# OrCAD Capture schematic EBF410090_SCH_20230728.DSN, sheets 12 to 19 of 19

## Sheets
12 16 MIPI CSI PORT: size A4; note: MIPI CSI PORT
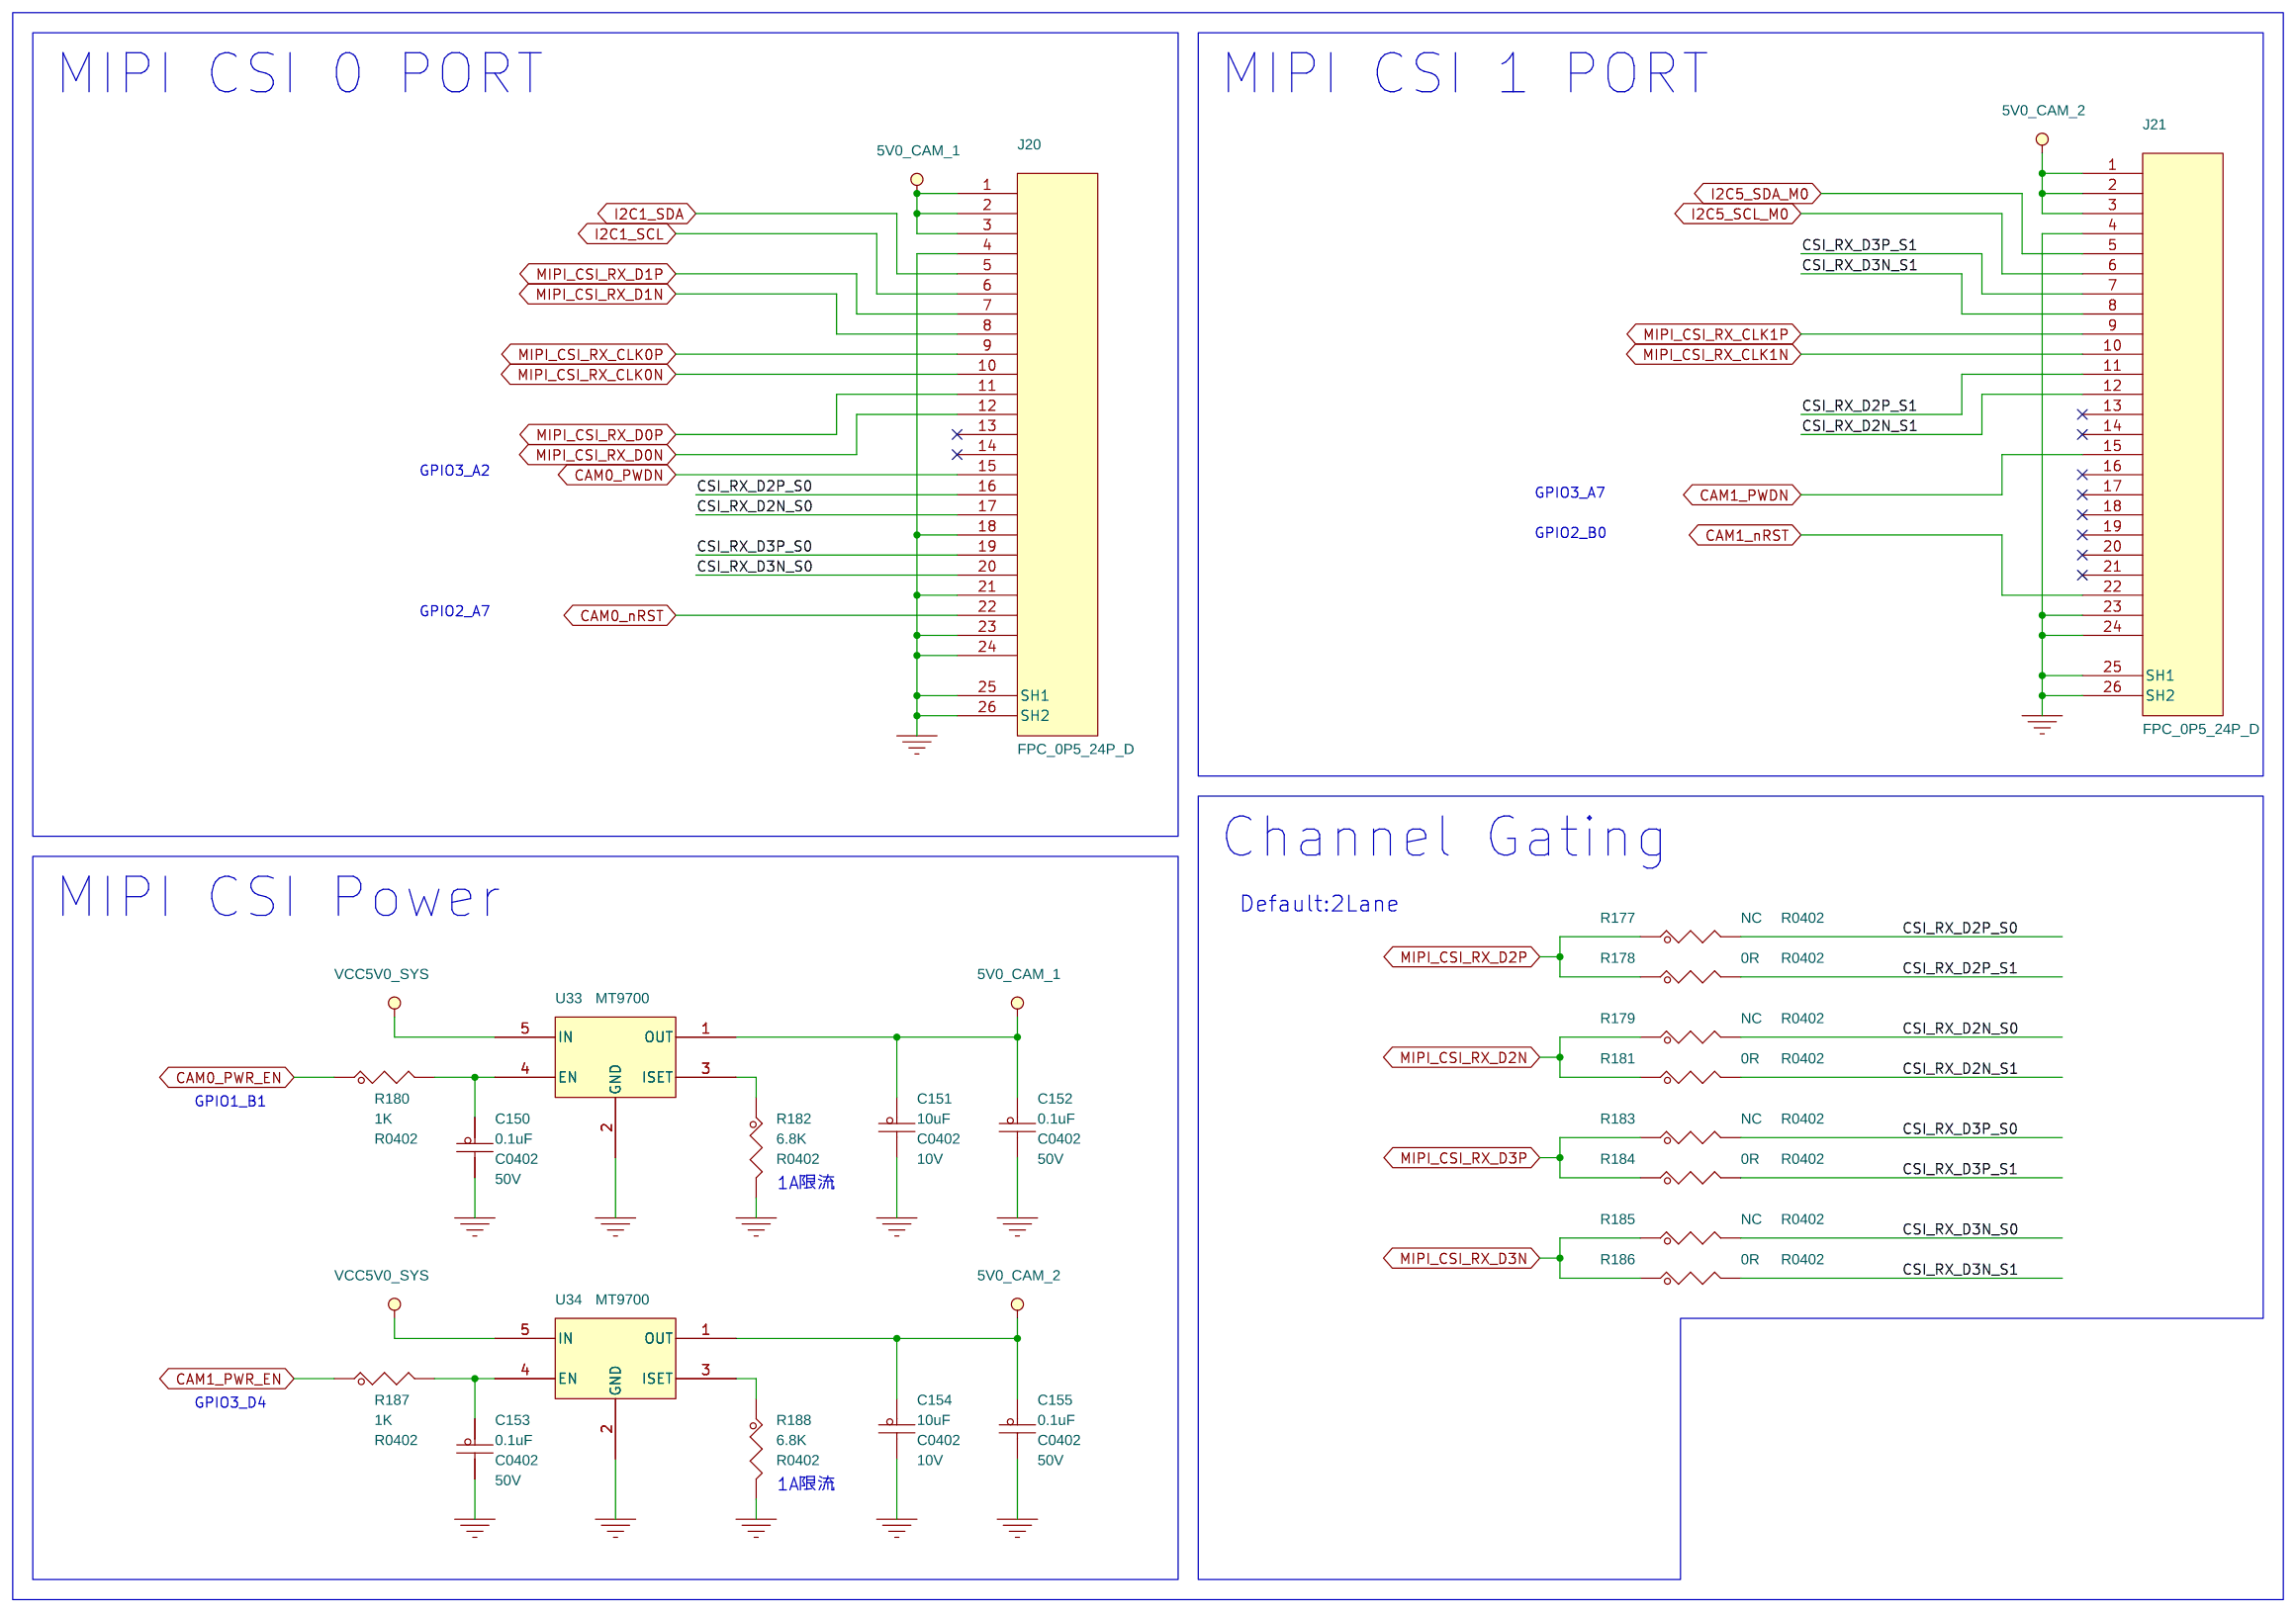
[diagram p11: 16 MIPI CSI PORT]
13 18 MINI PCIE_PORT: size A3; note: MINI PCIE PORT
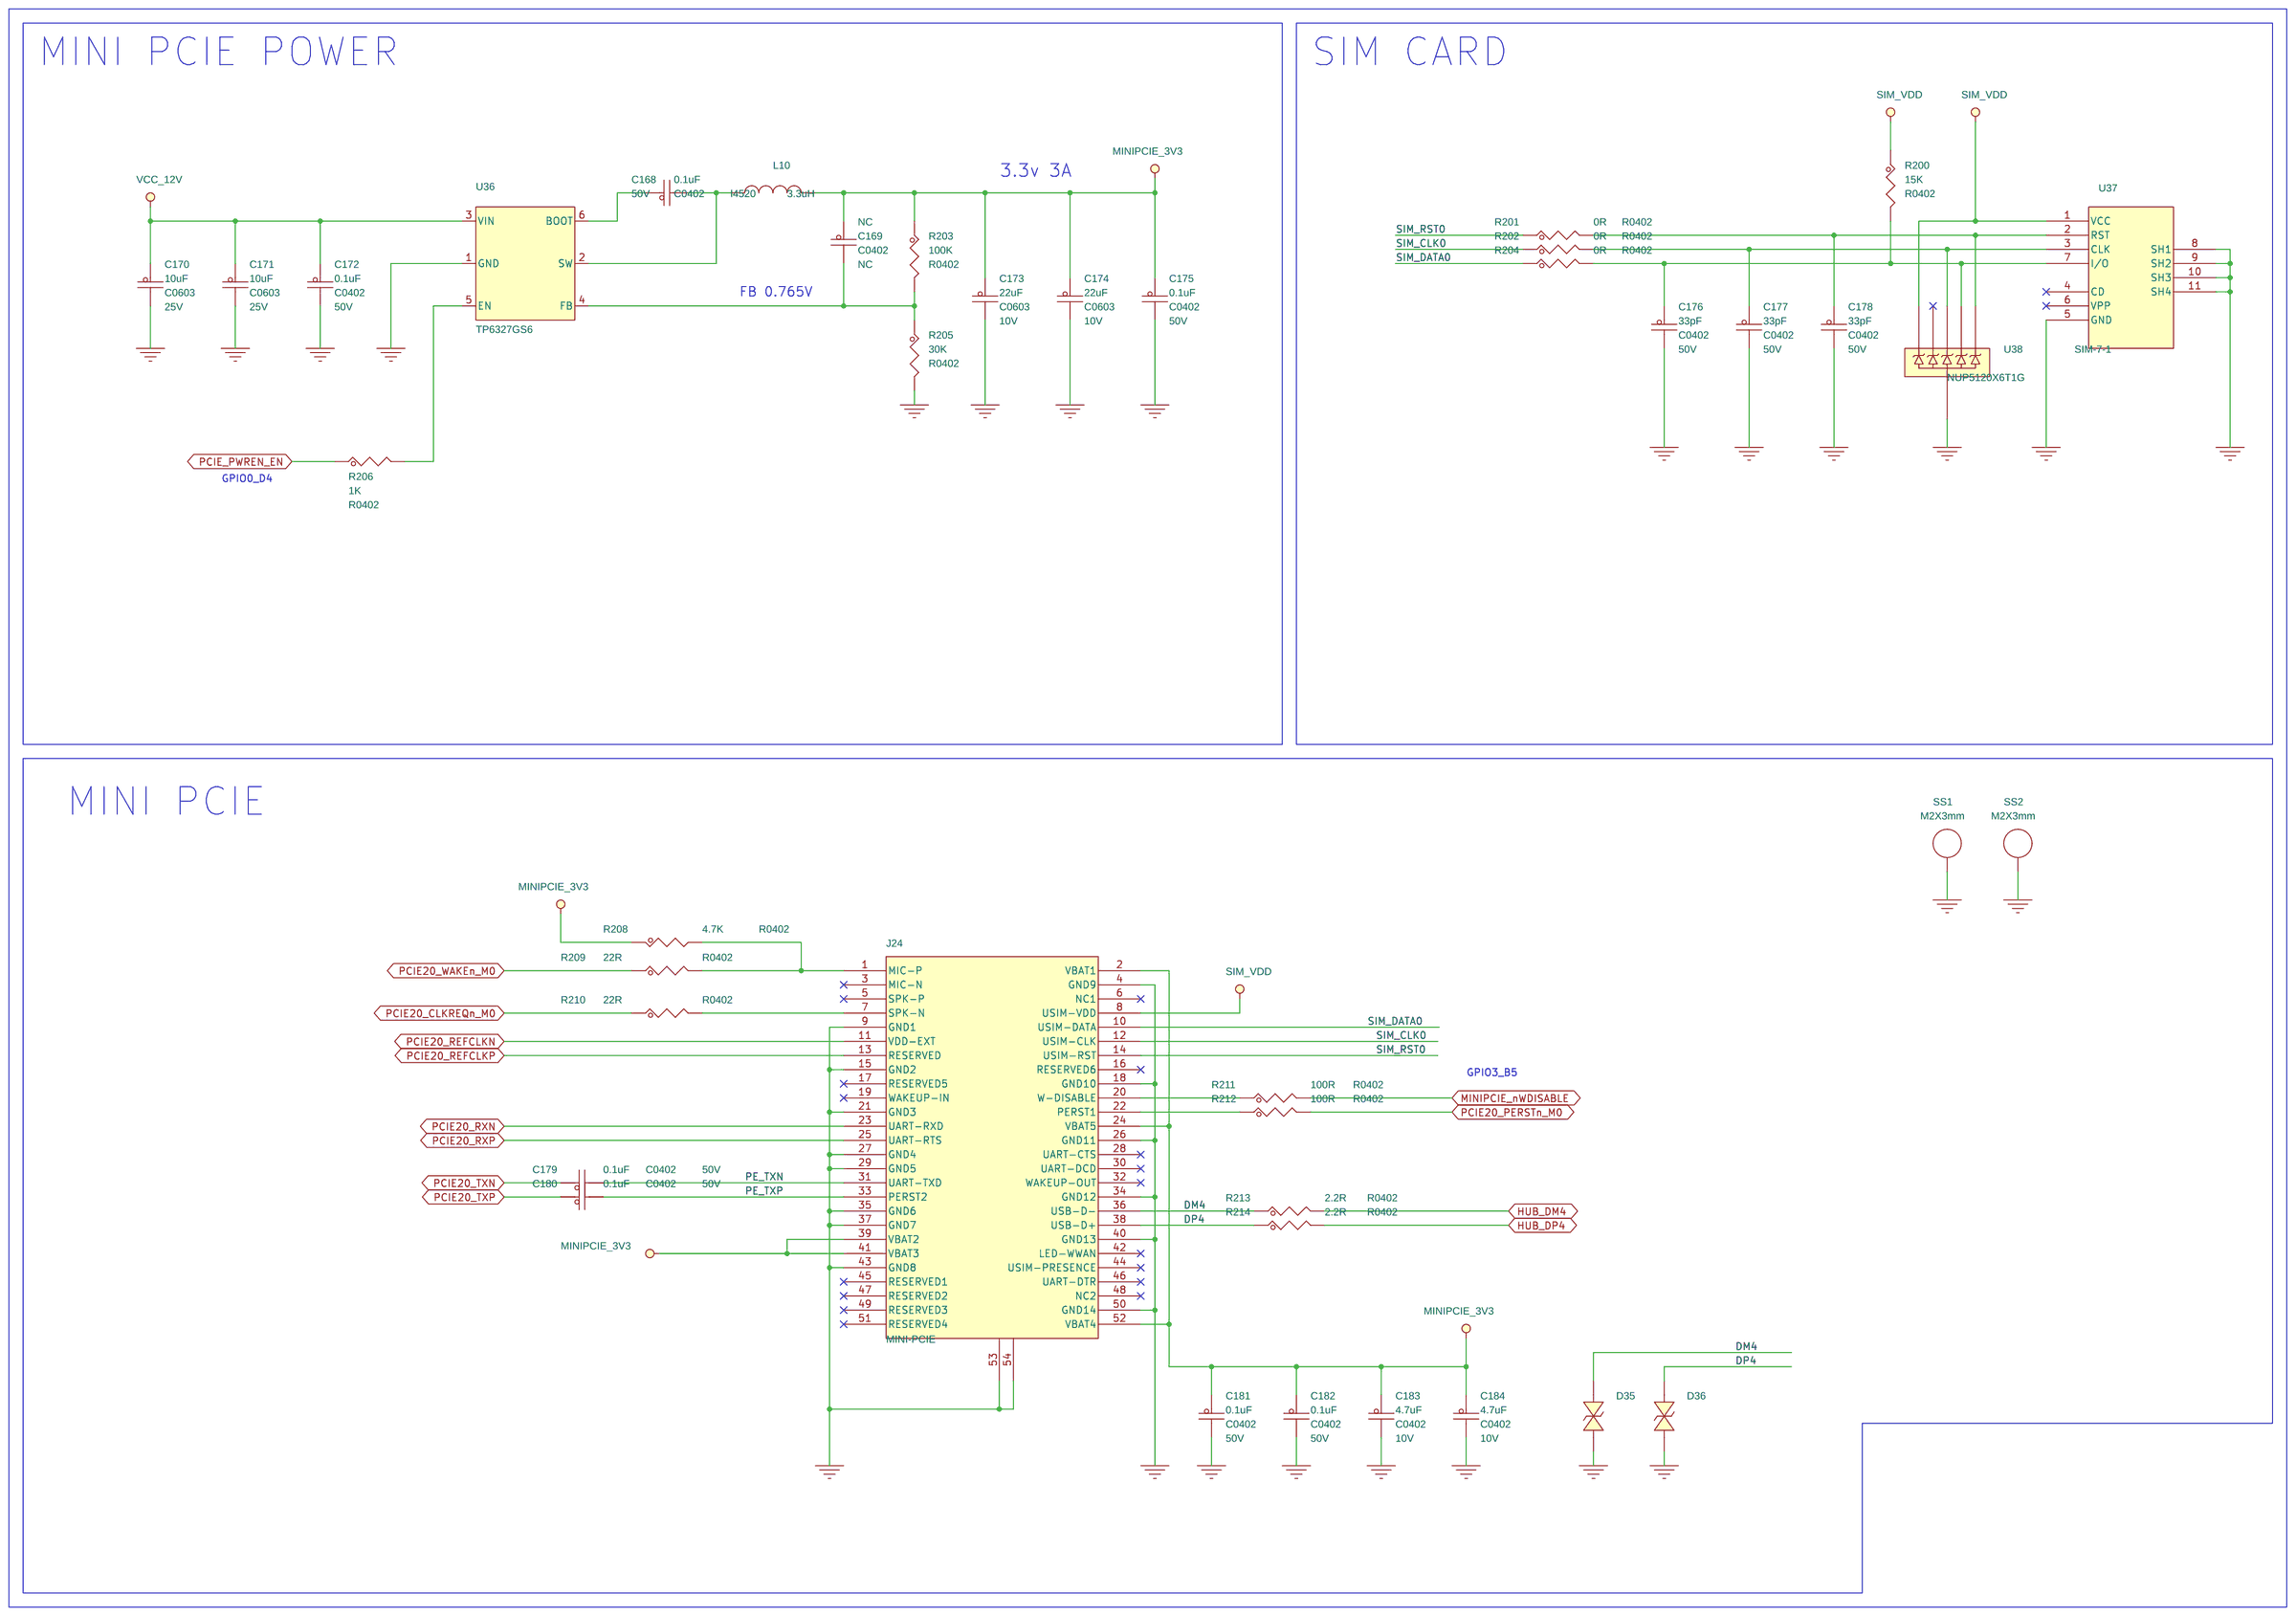
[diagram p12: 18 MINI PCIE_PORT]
14 19 AUDIO PORT: size A4; note: AUDIO PORT
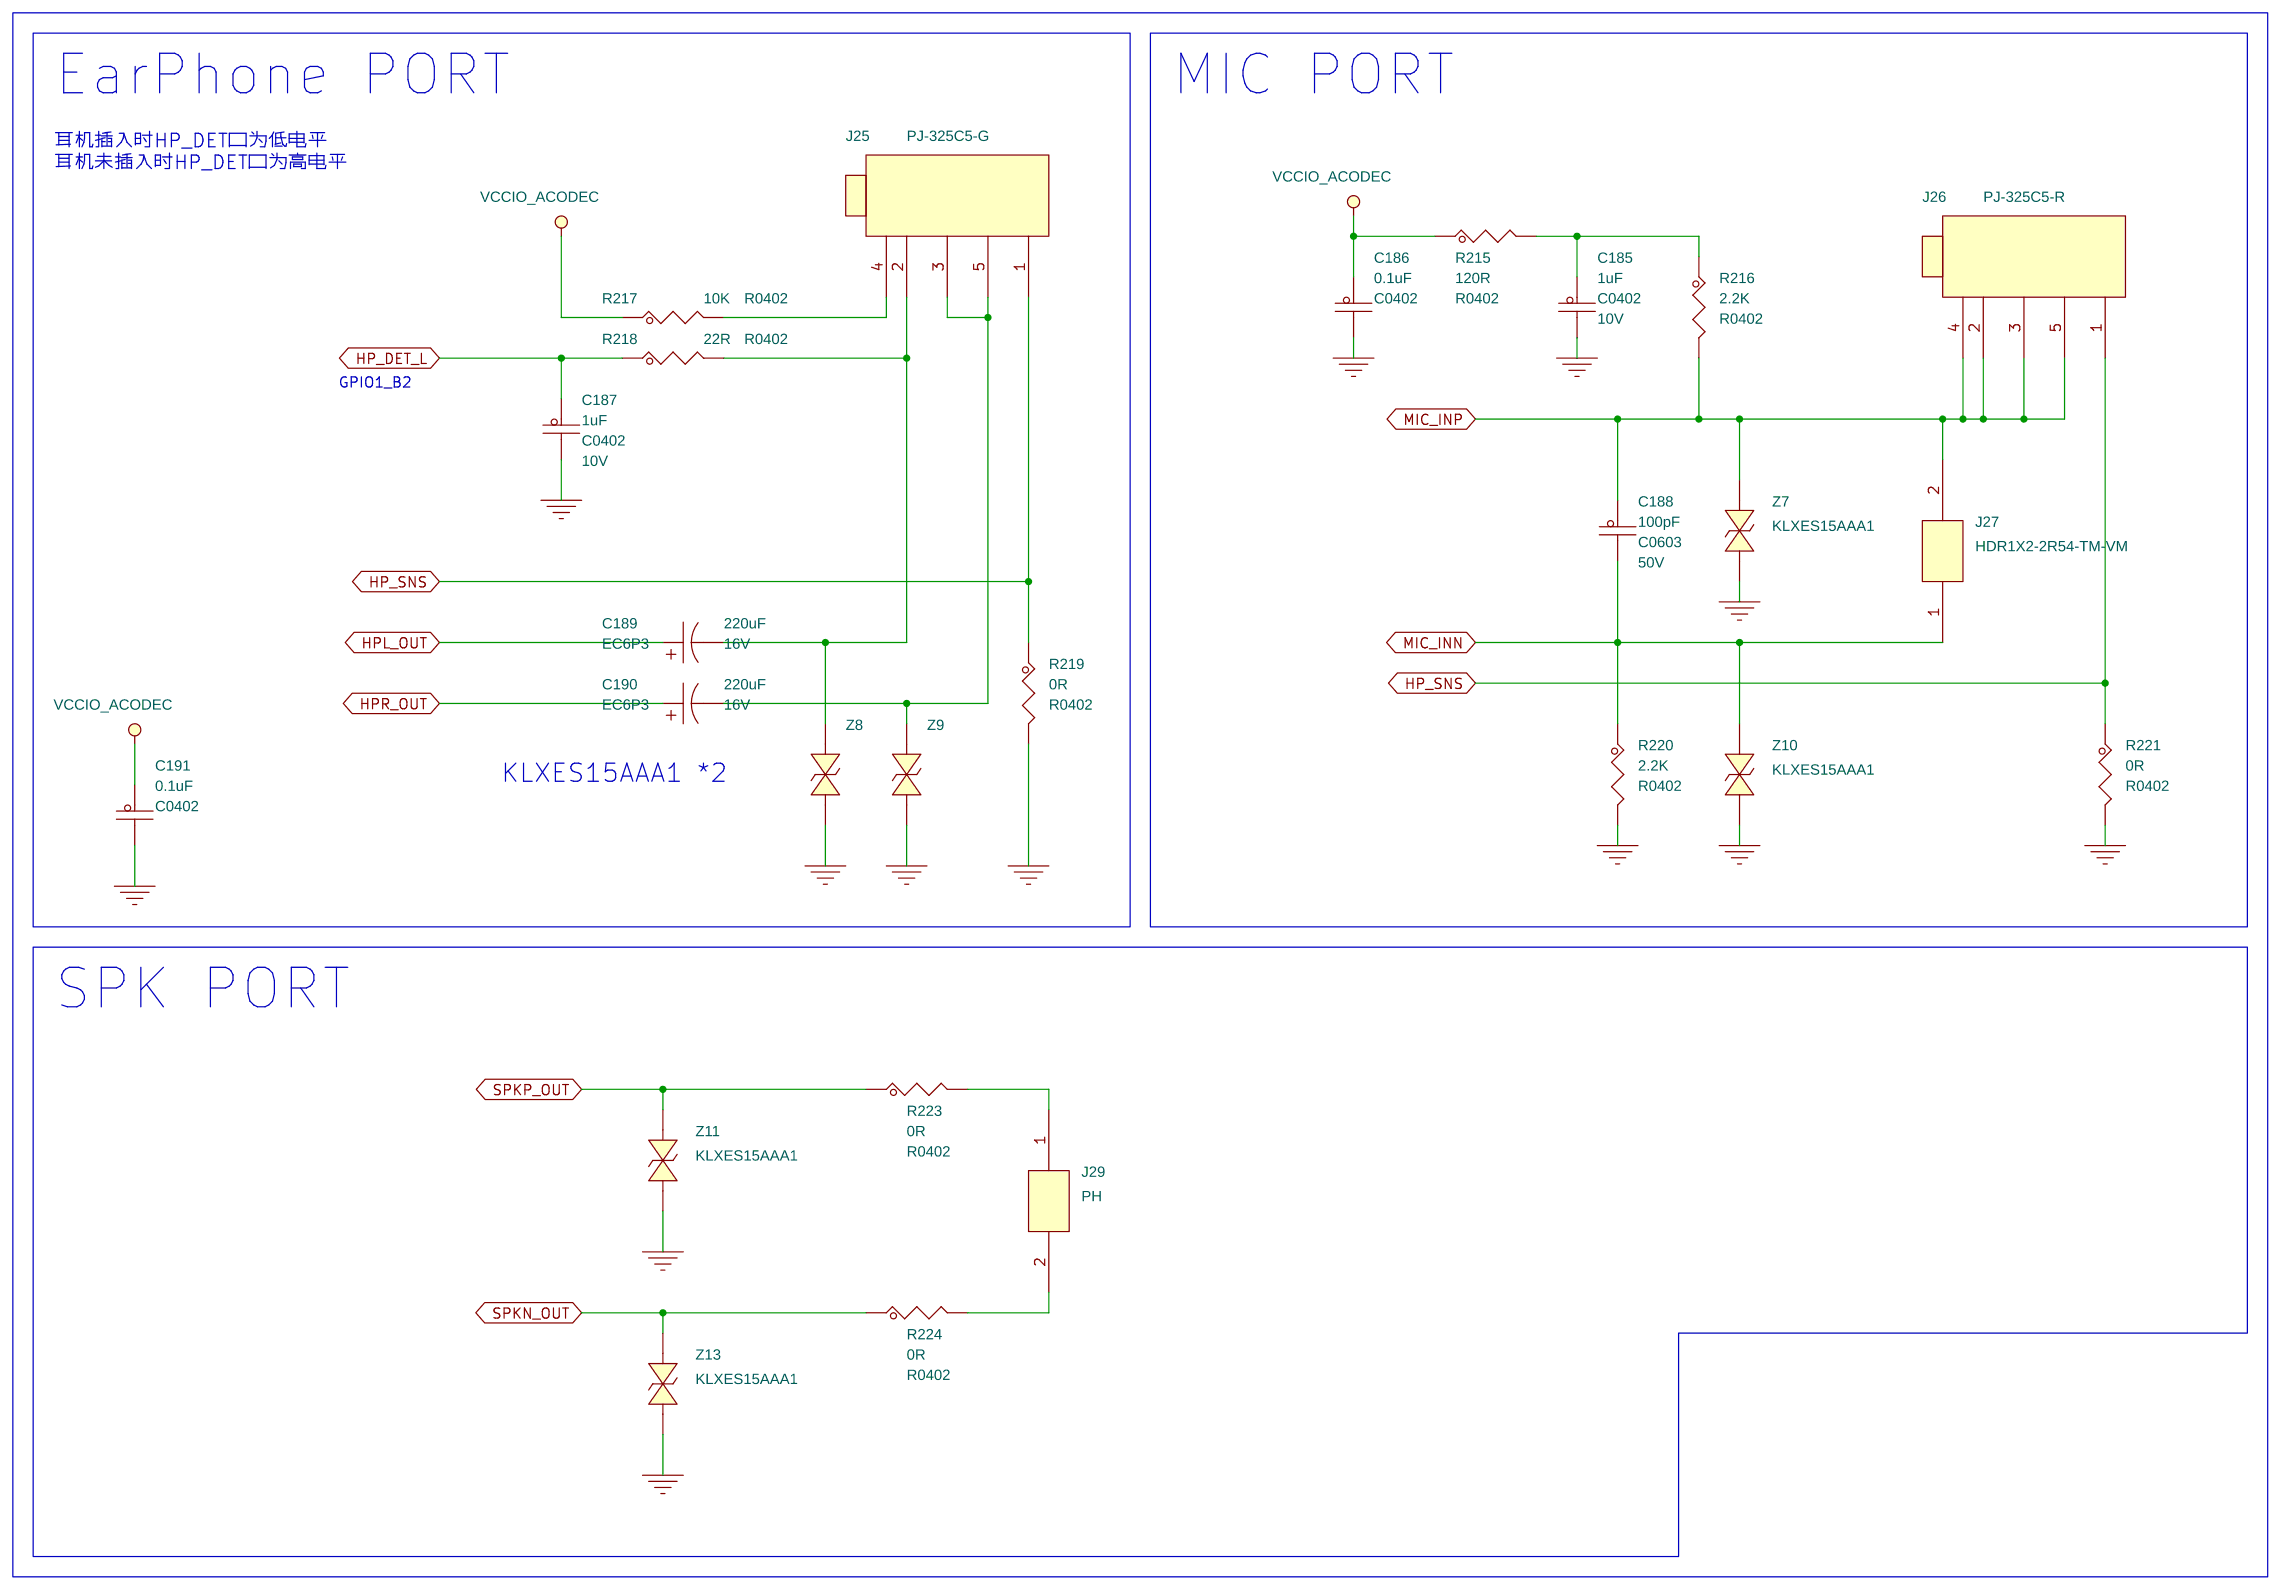
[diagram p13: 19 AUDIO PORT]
15 08 SD/RTC/RS232: size A3; note: SD/RTC/RS232
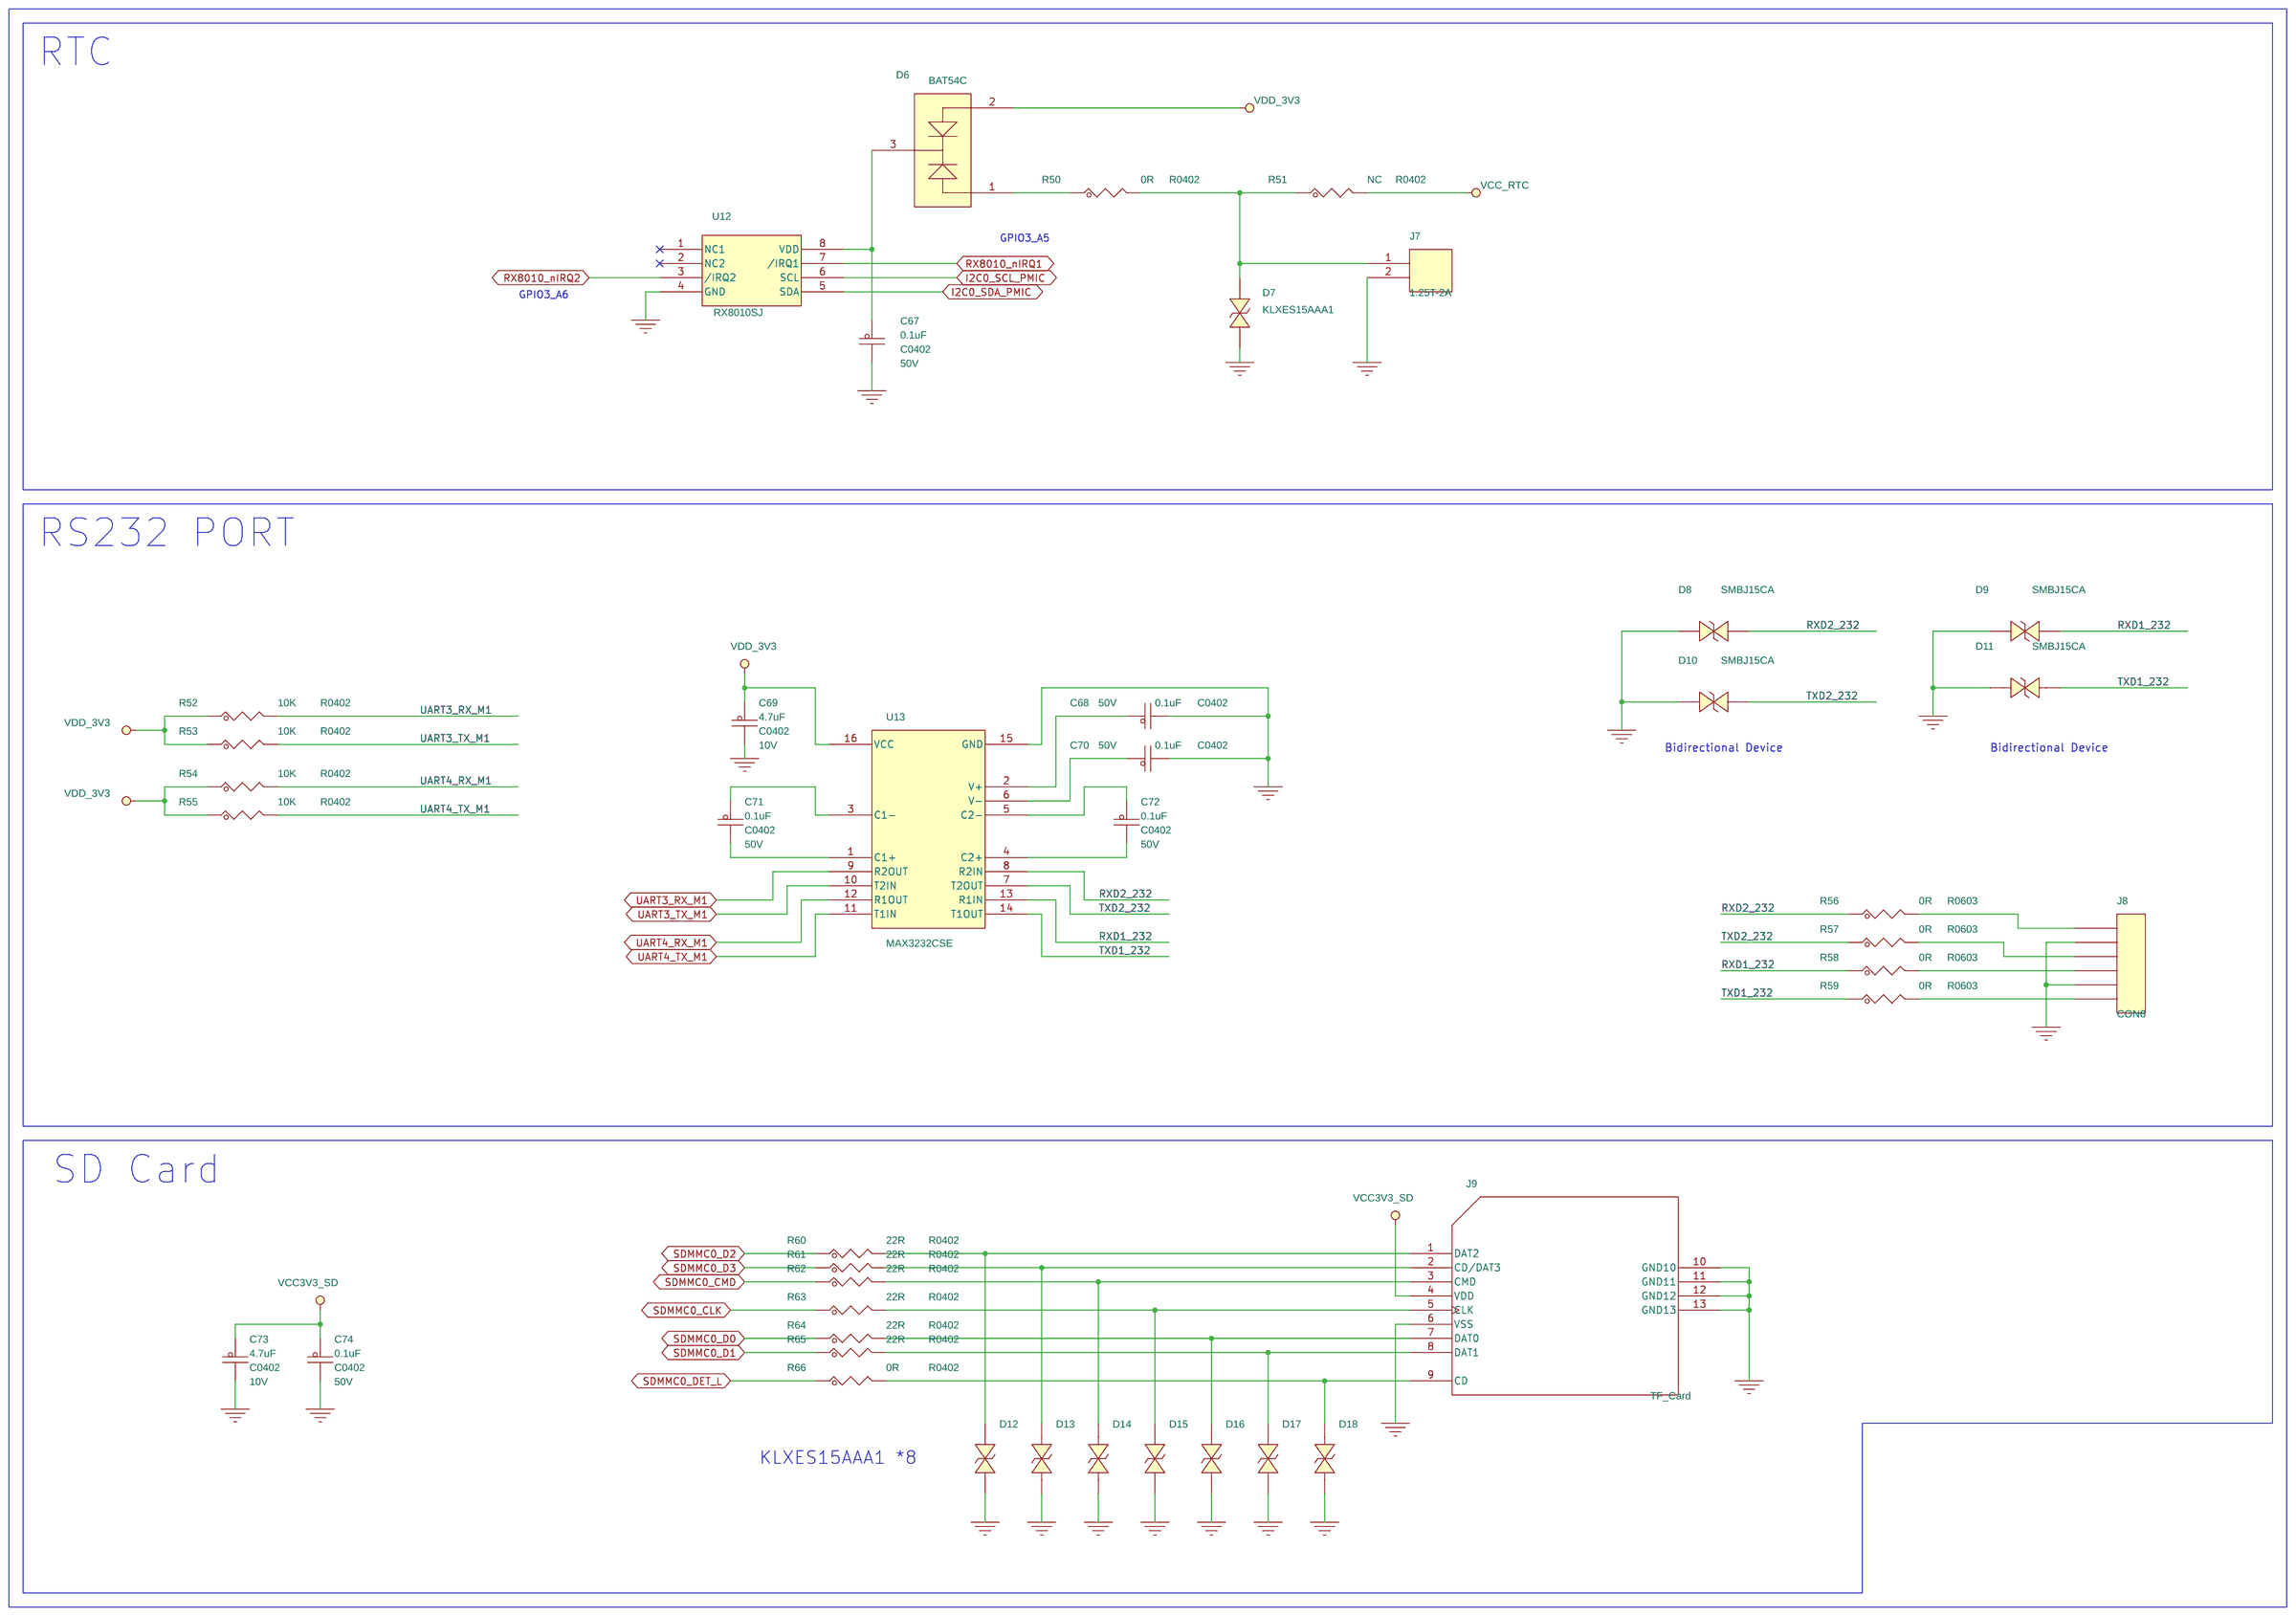
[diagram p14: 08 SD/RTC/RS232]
16 10 I2C/UART PORT: size A4; note: 40P  GPIO
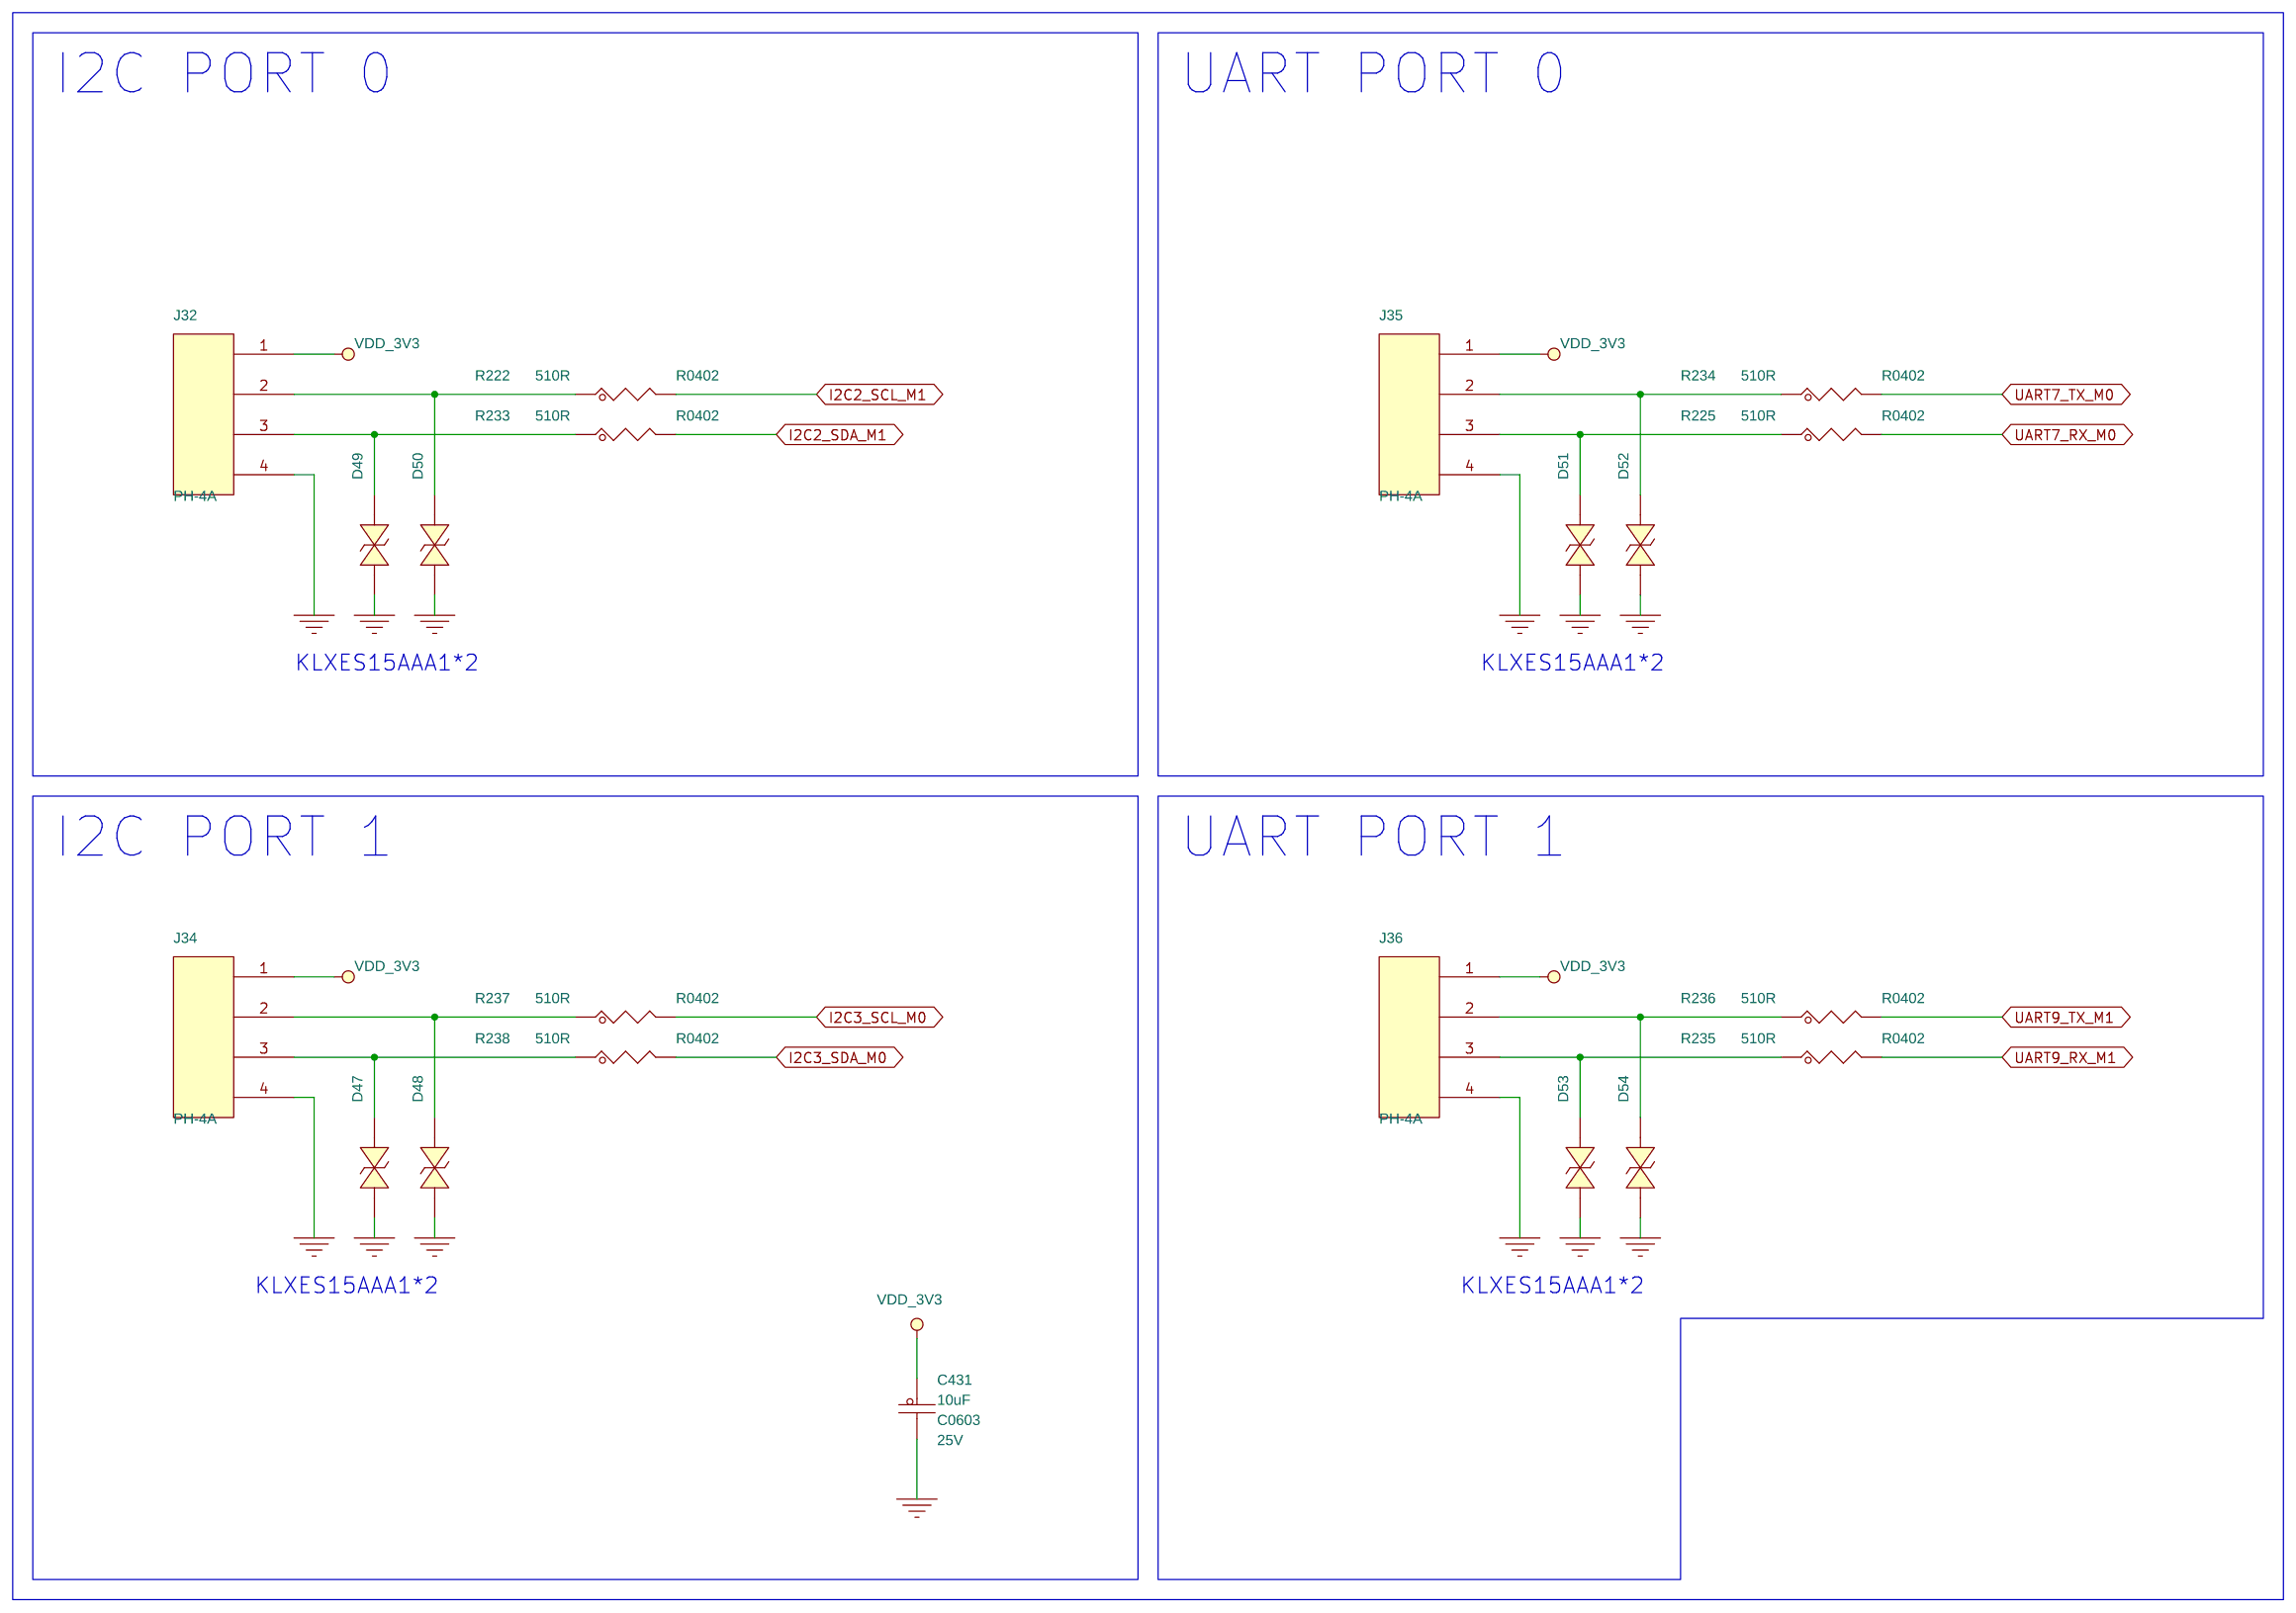
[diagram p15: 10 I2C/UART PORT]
17 04 DC IN/POWER/FAN: size A3; note: DC IN/POWER/FAN
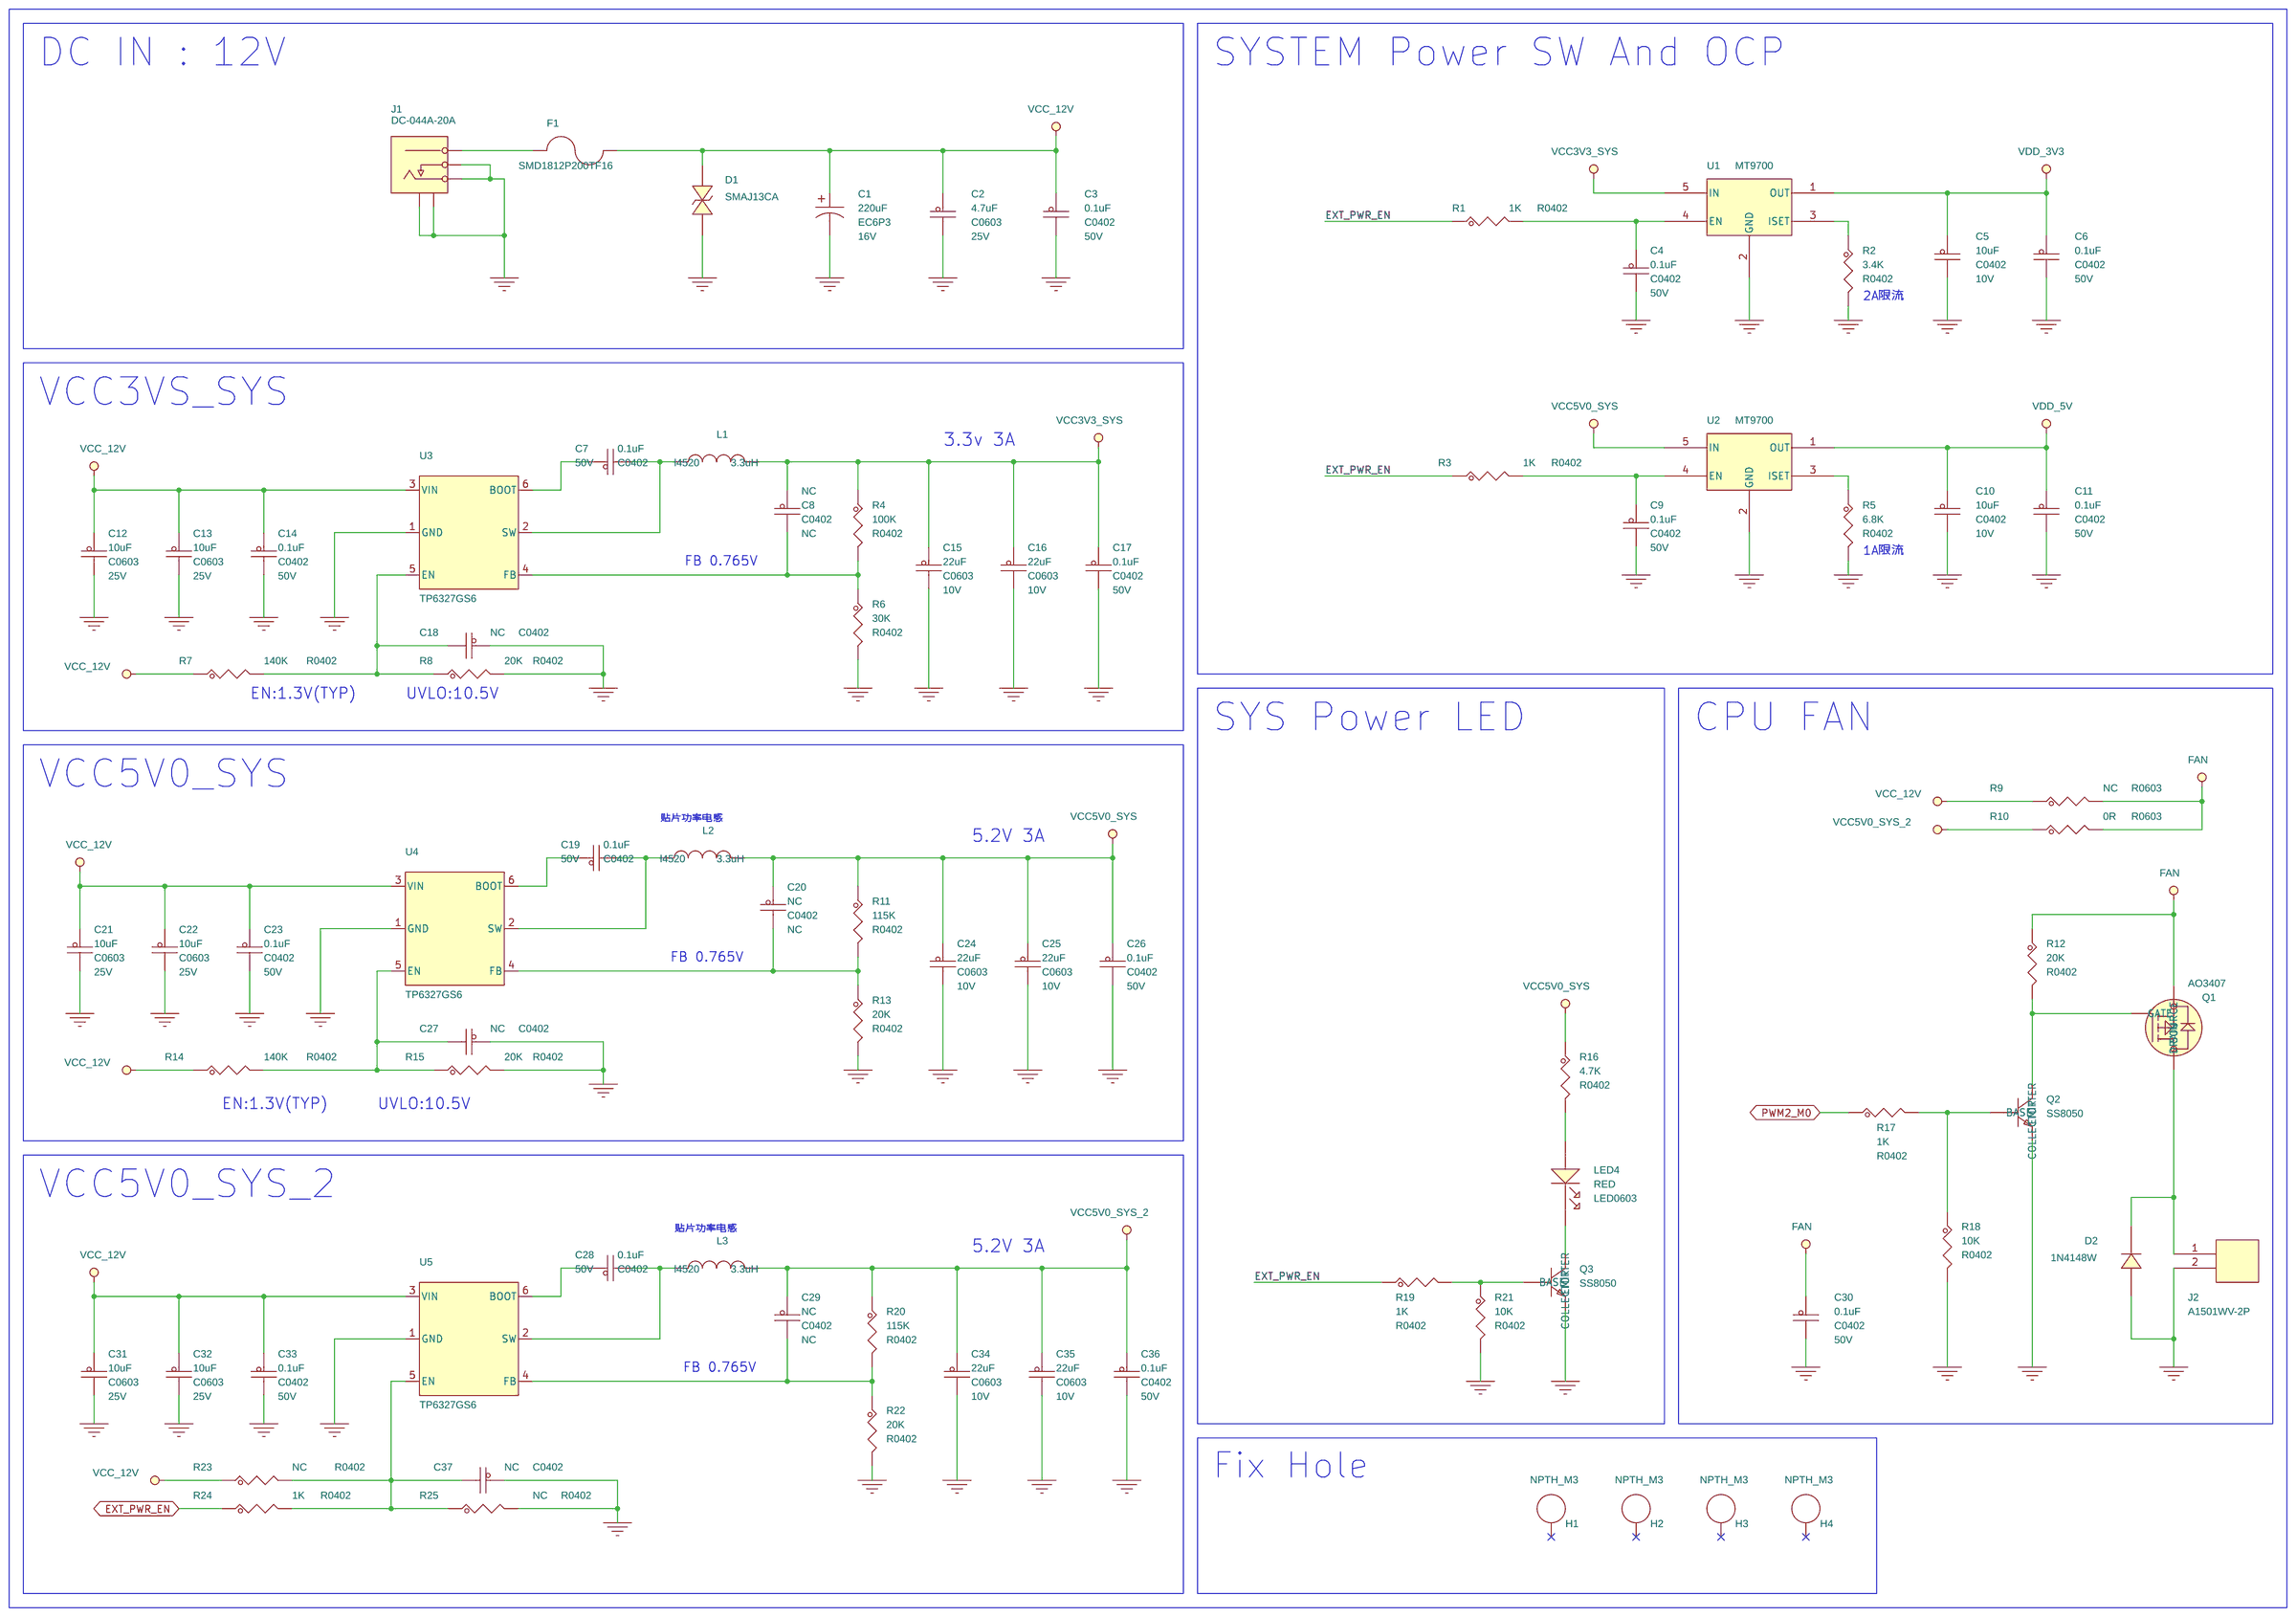
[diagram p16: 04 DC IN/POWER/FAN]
18 17 eDP_1.3/TP_PORT: size A4; note: eDP1.3/TP_PORT
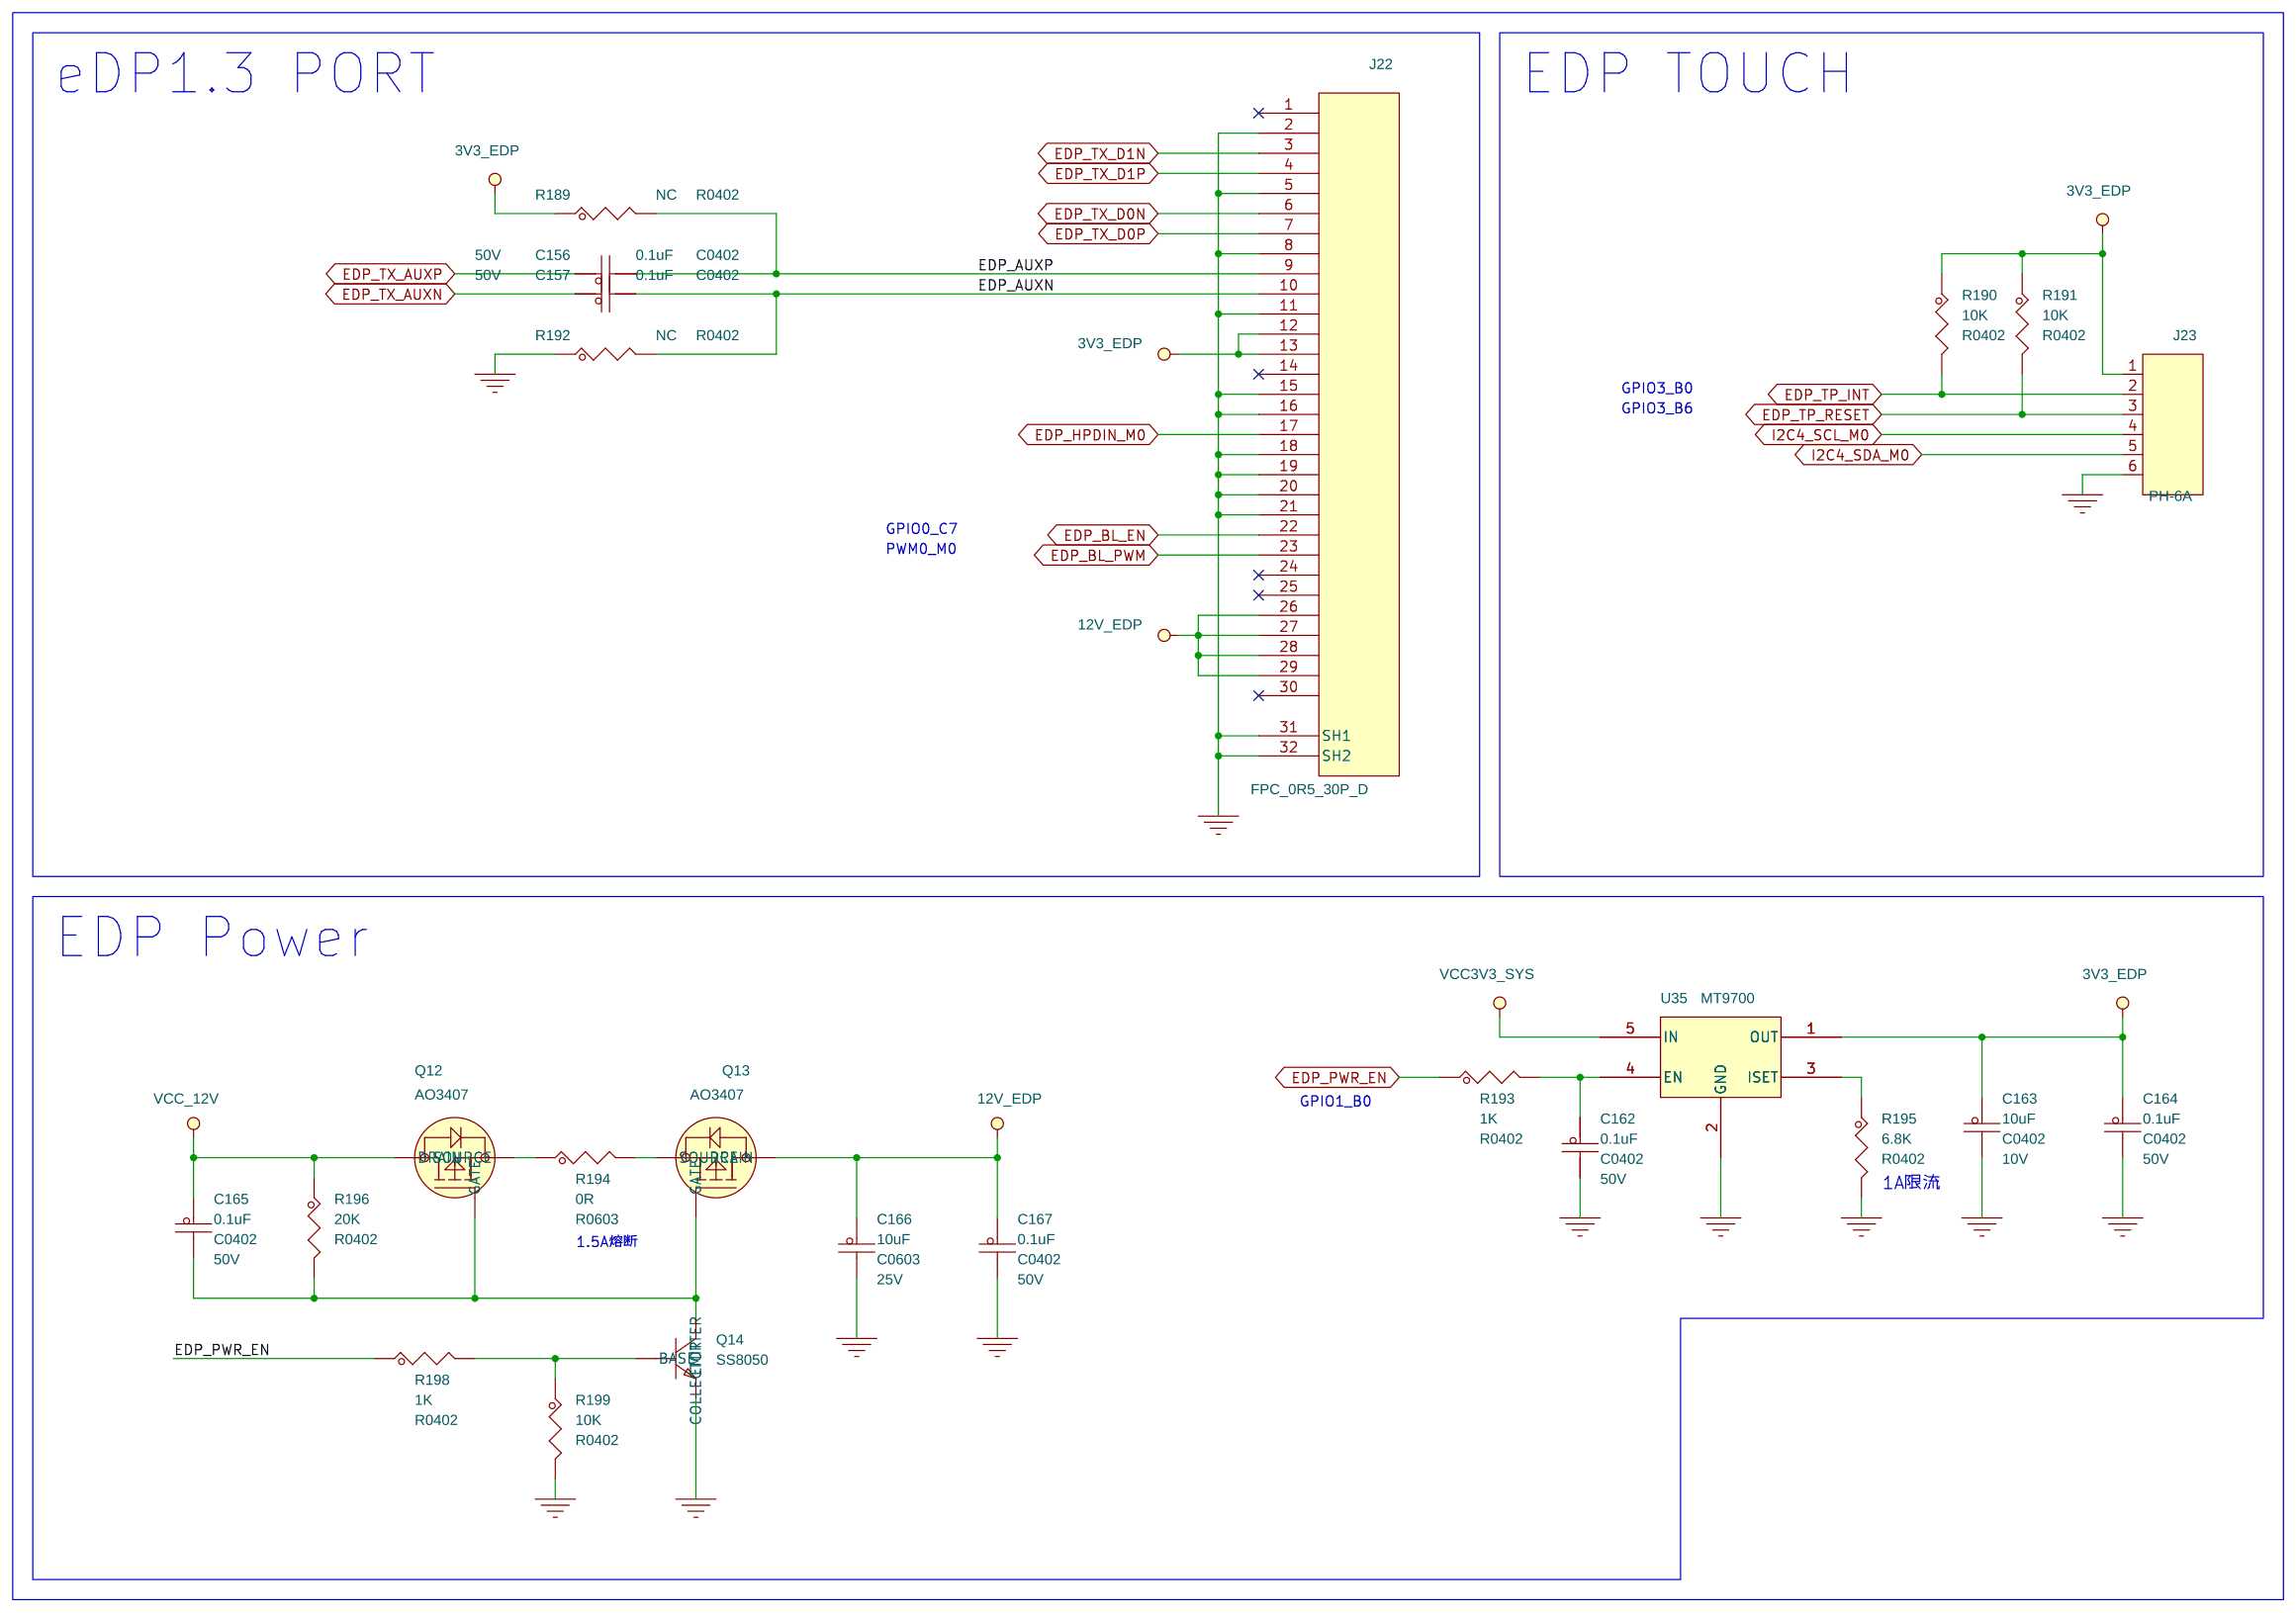
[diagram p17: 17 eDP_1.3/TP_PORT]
19 07 Button/FLASH/IR/DEBUG/LED: size A3; note: Button/FLASH/IR/DEBUG/LED
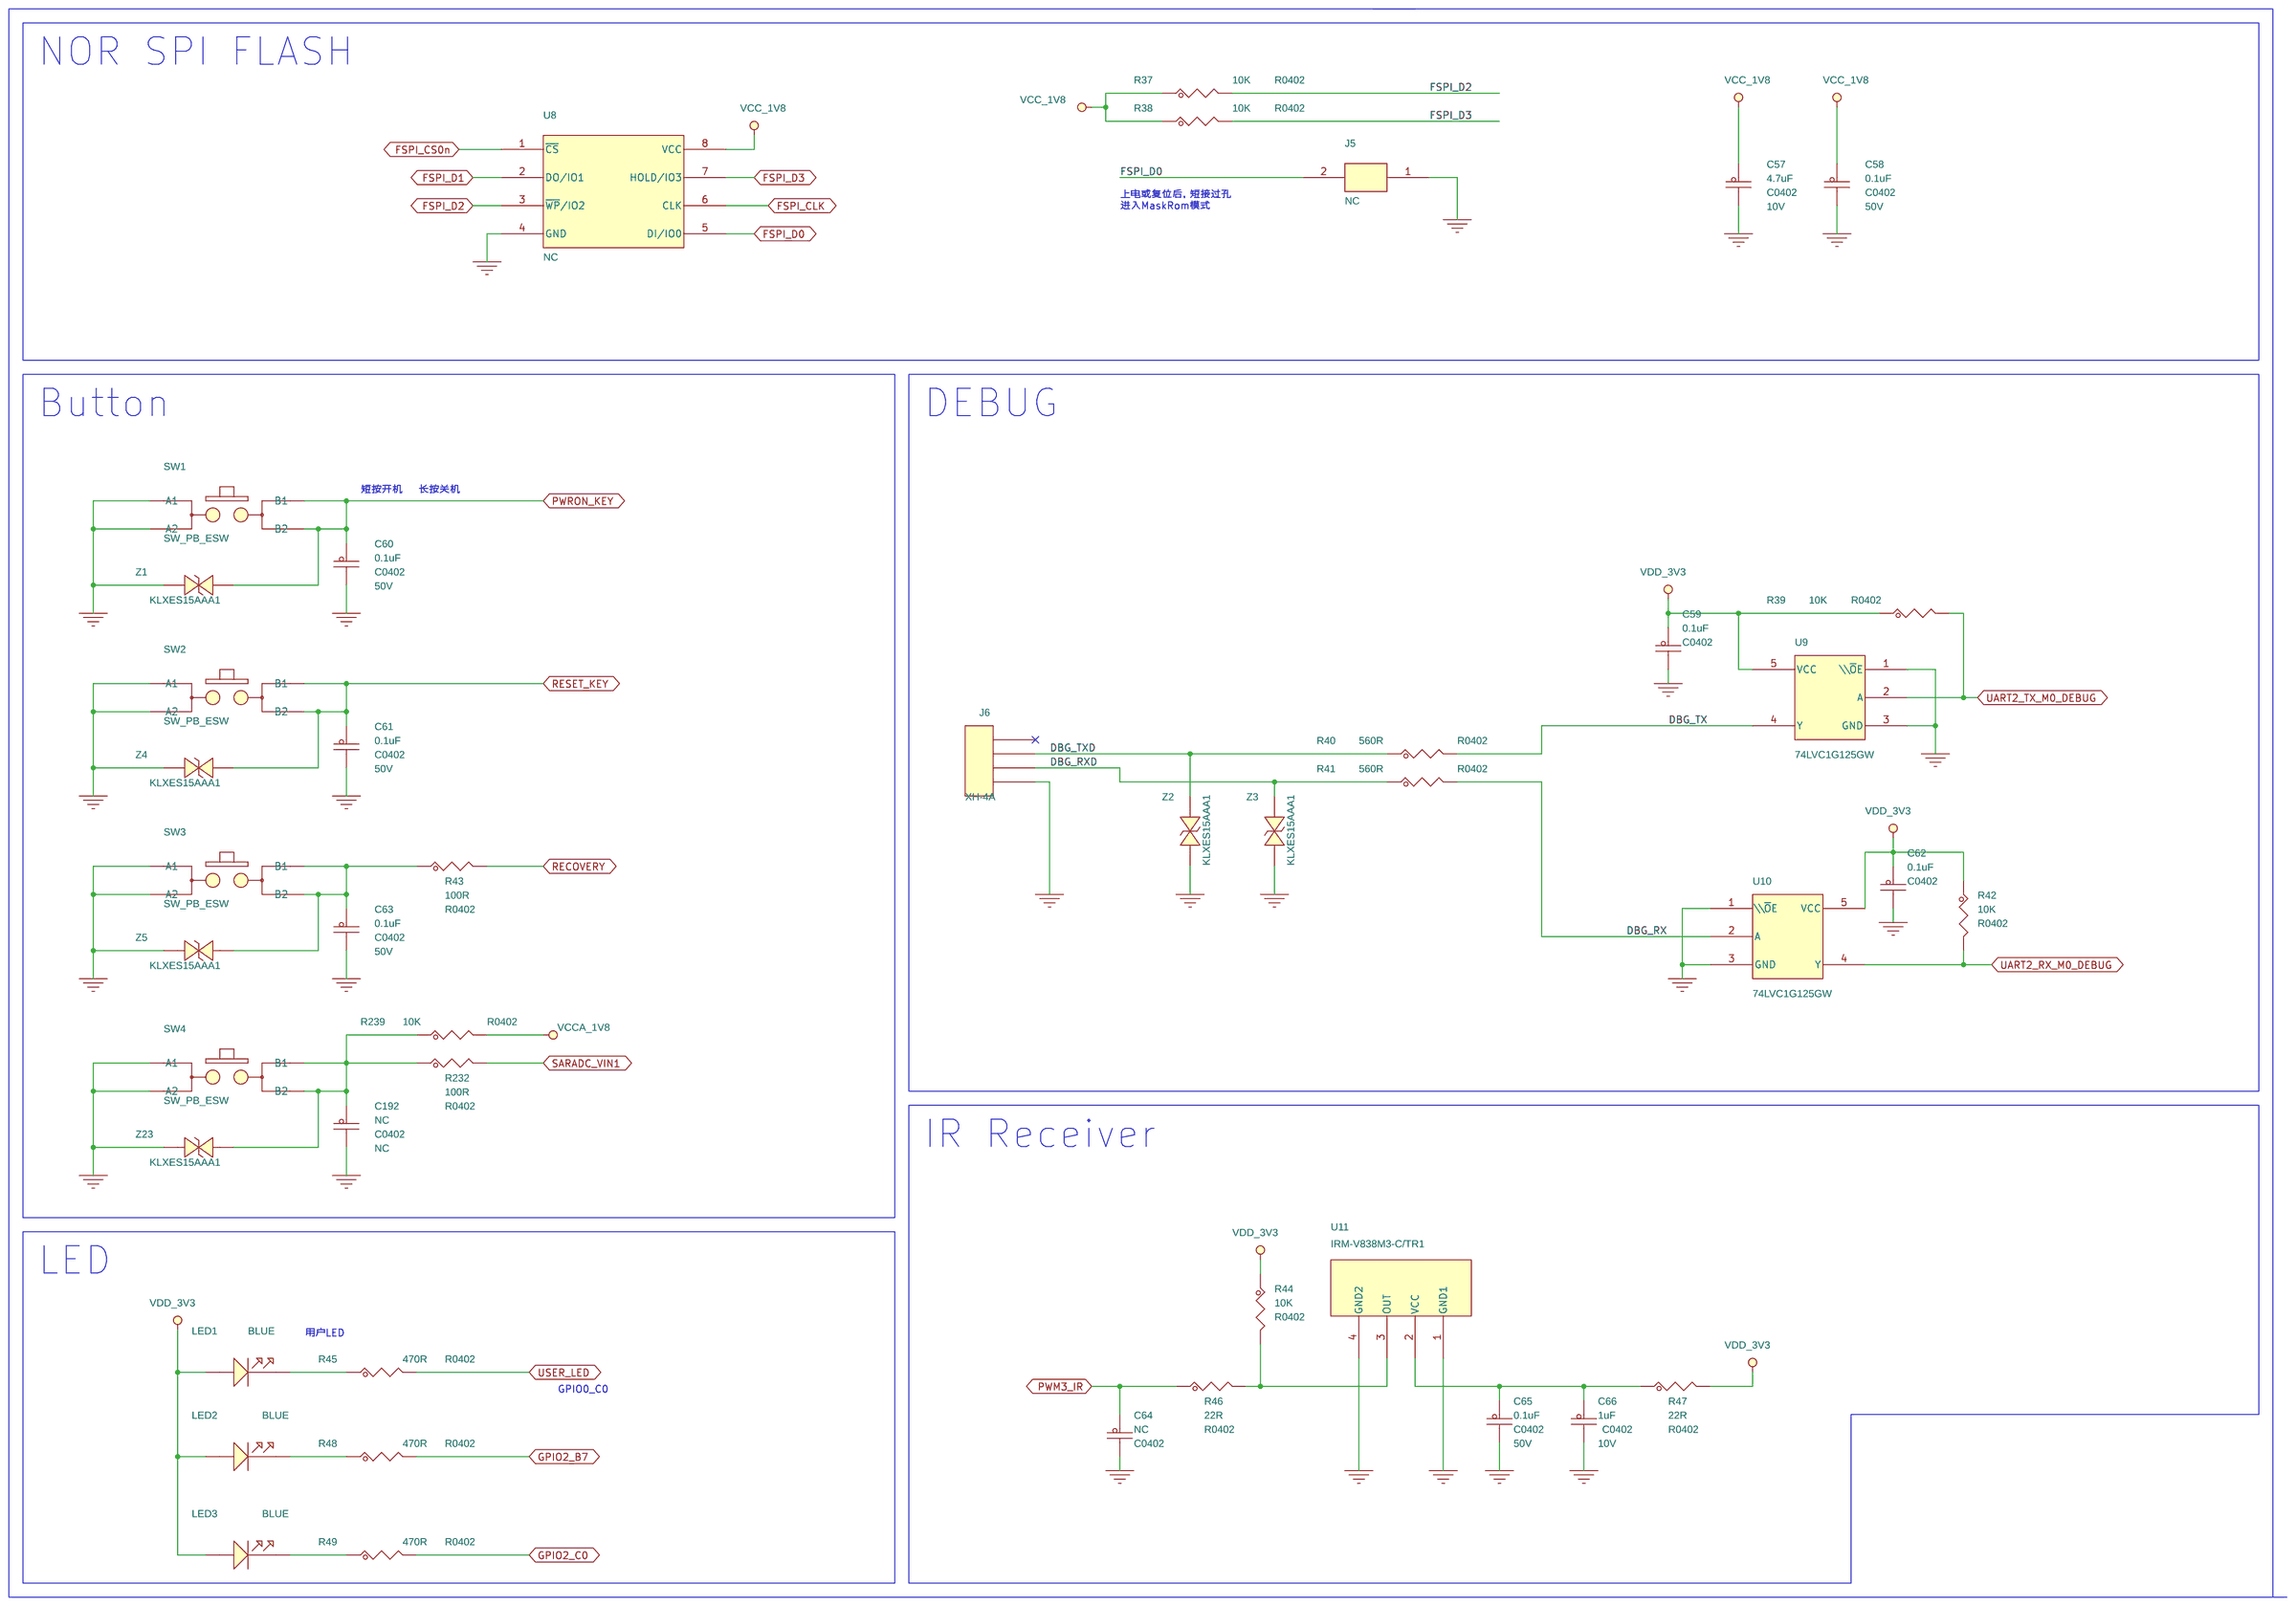
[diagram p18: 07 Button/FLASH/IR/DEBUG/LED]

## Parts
sheet 04 DC IN/POWER/FAN
C1  220uF  [EC6P3]
C2  4.7uF  [C0603]
C3  0.1uF  [C0402]
C4  0.1uF  [C0402]
C5  10uF  [C0402]
C6  0.1uF  [C0402]
C7  0.1uF  [C0402]
C8  NC  [C0402]
C9  0.1uF  [C0402]
C10  10uF  [C0402]
C11  0.1uF  [C0402]
C12  10uF  [C0603]
C13  10uF  [C0603]
C14  0.1uF  [C0402]
C15  22uF  [C0603]
C16  22uF  [C0603]
C17  0.1uF  [C0402]
C18  NC  [C0402]
C19  0.1uF  [C0402]
C20  NC  [C0402]
C21  10uF  [C0603]
C22  10uF  [C0603]
C23  0.1uF  [C0402]
C24  22uF  [C0603]
C25  22uF  [C0603]
C26  0.1uF  [C0402]
C27  NC  [C0402]
C28  0.1uF  [C0402]
C29  NC  [C0402]
C30  0.1uF  [C0402]
C31  10uF  [C0603]
C32  10uF  [C0603]
C33  0.1uF  [C0402]
C34  22uF  [C0603]
C35  22uF  [C0603]
C36  0.1uF  [C0402]
C37  NC  [C0402]
D1  SMAJ13CA  [SMA214-CA]
D2  1N4148W  [SOD-123]
F1  SMD1812P200TF16  [F1812]
H1  NPTH_M3  [NPTH_M3]
H2  NPTH_M3  [NPTH_M3]
H3  NPTH_M3  [NPTH_M3]
H4  NPTH_M3  [NPTH_M3]
J1  DC-044A-20A  [dc_in_th_3p_10r1x11r6]
J2  A1501WV-2P  [zh1p5mm_th_2p]
L1  3.3uH  [l4520]
L2  3.3uH  [l4520]
L3  3.3uH  [l4520]
LED4  RED  [LED0603]
Q1  AO3407  [SOT23]
Q2  SS8050  [SOT23]
Q3  SS8050  [SOT23]
R1  1K  [R0402]
R2  3.4K  [R0402]
R3  1K  [R0402]
R4  100K  [R0402]
R5  6.8K  [R0402]
R6  30K  [R0402]
R7  140K  [R0402]
R8  20K  [R0402]
R9  NC  [R0603]
R10  0R  [R0603]
R11  115K  [R0402]
R12  20K  [R0402]
R13  20K  [R0402]
R14  140K  [R0402]
R15  20K  [R0402]
R16  4.7K  [R0402]
R17  1K  [R0402]
R18  10K  [R0402]
R19  1K  [R0402]
R20  115K  [R0402]
R21  10K  [R0402]
R22  20K  [R0402]
R23  NC  [R0402]
R24  1K  [R0402]
R25  NC  [R0402]
U1  MT9700  [SOT23-5]
U2  MT9700  [SOT23-5]
U3  TP6327GS6  [SOT23_6]
U4  TP6327GS6  [SOT23_6]
U5  TP6327GS6  [SOT23_6]
sheet 07 Button/FLASH/IR/DEBUG/LED
C57  4.7uF  [C0402]
C58  0.1uF  [C0402]
C59  0.1uF  [C0402]
C60  0.1uF  [C0402]
C61  0.1uF  [C0402]
C62  0.1uF  [C0402]
C63  0.1uF  [C0402]
C64  NC  [C0402]
C65  0.1uF  [C0402]
C66  1uF  [C0402]
C192  NC  [C0402]
J5  NC  [HDR1X2-2R54-TM-VM]
J6  XH-4A  [XH2p54-4p]
LED1  BLUE  [LED0603]
LED2  BLUE  [LED0603]
LED3  BLUE  [LED0603]
R37  10K  [R0402]
R38  10K  [R0402]
R39  10K  [R0402]
R40  560R  [R0402]
R41  560R  [R0402]
R42  10K  [R0402]
R43  100R  [R0402]
R44  10K  [R0402]
R45  470R  [R0402]
R46  22R  [R0402]
R47  22R  [R0402]
R48  470R  [R0402]
R49  470R  [R0402]
R232  100R  [R0402]
R239  10K  [R0402]
SW1  SW_PB_ESW  [SW4-4R20X3R25-SM]
SW2  SW_PB_ESW  [SW4-4R20X3R25-SM]
SW3  SW_PB_ESW  [SW4-4R20X3R25-SM]
SW4  SW_PB_ESW  [SW4-4R20X3R25-SM]
U8  NC  [SOIC8-208]
U9  74LVC1G125GW  [SOT-353]
U10  74LVC1G125GW  [SOT-353]
U11  IRM-V838M3-C/TR1  [SMD4-6R80X2R50]
Z1  KLXES15AAA1  [ES0402]
Z2  KLXES15AAA1  [ES0402]
Z3  KLXES15AAA1  [ES0402]
Z4  KLXES15AAA1  [ES0402]
Z5  KLXES15AAA1  [ES0402]
Z23  KLXES15AAA1  [ES0402]
sheet 08 SD/RTC/RS232
C67  0.1uF  [C0402]
C68  0.1uF  [C0402]
C69  4.7uF  [C0402]
C70  0.1uF  [C0402]
C71  0.1uF  [C0402]
C72  0.1uF  [C0402]
C73  4.7uF  [C0402]
C74  0.1uF  [C0402]
D6  BAT54C  [SOT23]
D7  KLXES15AAA1  [ES0402]
D8  SMBJ15CA  [SMB-CA]
D9  SMBJ15CA  [SMB-CA]
D10  SMBJ15CA  [SMB-CA]
D11  SMBJ15CA  [SMB-CA]
D12  KLXES15AAA1  [ES0402]
D13  KLXES15AAA1  [ES0402]
D14  KLXES15AAA1  [ES0402]
D15  KLXES15AAA1  [ES0402]
D16  KLXES15AAA1  [ES0402]
D17  KLXES15AAA1  [ES0402]
D18  KLXES15AAA1  [ES0402]
J7  1.25T-2A  [gh1p25_th_2p]
J8  CON6  [DB2ERC-3P81-6P]
J9  TF_Card  [TFCARD]
R50  0R  [R0402]
R51  NC  [R0402]
R52  10K  [R0402]
R53  10K  [R0402]
R54  10K  [R0402]
R55  10K  [R0402]
R56  0R  [R0603]
R57  0R  [R0603]
R58  0R  [R0603]
R59  0R  [R0603]
R60  22R  [R0402]
R61  22R  [R0402]
R62  22R  [R0402]
R63  22R  [R0402]
R64  22R  [R0402]
R65  22R  [R0402]
R66  0R  [R0402]
U12  RX8010SJ  [SOP8]
U13  MAX3232CSE  [SOIC16]
sheet 10 I2C/UART PORT
C431  10uF  [C0603]
D47  KLXES15AAA1  [ES0402]
D48  KLXES15AAA1  [ES0402]
D49  KLXES15AAA1  [ES0402]
D50  KLXES15AAA1  [ES0402]
D51  KLXES15AAA1  [ES0402]
D52  KLXES15AAA1  [ES0402]
D53  KLXES15AAA1  [ES0402]
D54  KLXES15AAA1  [ES0402]
J32  PH-4A  [PH-1X4-2P0]
J34  PH-4A  [PH-1X4-2P0]
J35  PH-4A  [PH-1X4-2P0]
J36  PH-4A  [PH-1X4-2P0]
R222  510R  [R0402]
R225  510R  [R0402]
R233  510R  [R0402]
R234  510R  [R0402]
R235  510R  [R0402]
R236  510R  [R0402]
R237  510R  [R0402]
R238  510R  [R0402]
sheet 16 MIPI CSI PORT
C150  0.1uF  [C0402]
C151  10uF  [C0402]
C152  0.1uF  [C0402]
C153  0.1uF  [C0402]
C154  10uF  [C0402]
C155  0.1uF  [C0402]
J20  FPC_0P5_24P_D  [fpc_24p_0p5]
J21  FPC_0P5_24P_D  [fpc_24p_0p5]
R177  NC  [R0402]
R178  0R  [R0402]
R179  NC  [R0402]
R180  1K  [R0402]
R181  0R  [R0402]
R182  6.8K  [R0402]
R183  NC  [R0402]
R184  0R  [R0402]
R185  NC  [R0402]
R186  0R  [R0402]
R187  1K  [R0402]
R188  6.8K  [R0402]
U33  MT9700  [SOT23-5]
U34  MT9700  [SOT23-5]
sheet 17 eDP_1.3/TP_PORT
C156  0.1uF  [C0402]
C157  0.1uF  [C0402]
C162  0.1uF  [C0402]
C163  10uF  [C0402]
C164  0.1uF  [C0402]
C165  0.1uF  [C0402]
C166  10uF  [C0603]
C167  0.1uF  [C0402]
J22  FPC_0R5_30P_D  [FPC-30P-0P5]
J23  PH-6A  [PH-1X6-2P0]
Q12  AO3407  [SOT23]
Q13  AO3407  [SOT23]
Q14  SS8050  [SOT23]
R189  NC  [R0402]
R190  10K  [R0402]
R191  10K  [R0402]
R192  NC  [R0402]
R193  1K  [R0402]
R194  0R  [R0603]
R195  6.8K  [R0402]
R196  20K  [R0402]
R198  1K  [R0402]
R199  10K  [R0402]
U35  MT9700  [SOT23-5]
sheet 18 MINI PCIE_PORT
C168  0.1uF  [C0402]
C169  NC  [C0402]
C170  10uF  [C0603]
C171  10uF  [C0603]
C172  0.1uF  [C0402]
C173  22uF  [C0603]
C174  22uF  [C0603]
C175  0.1uF  [C0402]
C176  33pF  [C0402]
C177  33pF  [C0402]
C178  33pF  [C0402]
C179  0.1uF  [C0402]
C180  0.1uF  [C0402]
C181  0.1uF  [C0402]
C182  0.1uF  [C0402]
C183  4.7uF  [C0402]
C184  4.7uF  [C0402]
D35  KLXES15AAA1  [ES0402]
D36  KLXES15AAA1  [ES0402]
J24  MINI-PCIE  [pcie_52p]
L10  3.3uH  [l4520]
R200  15K  [R0402]
R201  0R  [R0402]
R202  0R  [R0402]
R203  100K  [R0402]
R204  0R  [R0402]
R205  30K  [R0402]
R206  1K  [R0402]
R208  4.7K  [R0402]
R209  22R  [R0402]
R210  22R  [R0402]
R211  100R  [R0402]
R212  100R  [R0402]
R213  2.2R  [R0402]
R214  2.2R  [R0402]
SS1  M2X3mm  [t3r2-5r2_topsmt]
SS2  M2X3mm  [t3r2-5r2_topsmt]
U36  TP6327GS6  [SOT23_6]
U37  SIM-7-1  [nano_sim]
U38  NUP5120X6T1G  [SOT563]
sheet 19 AUDIO PORT
C185  1uF  [C0402]
C186  0.1uF  [C0402]
C187  1uF  [C0402]
C188  100pF  [C0603]
C189  220uF  [EC6P3]
C190  220uF  [EC6P3]
C191  0.1uF  [C0402]
J25  PJ-325C5-G  [EAR_JACK]
J26  PJ-325C5-R  [EAR_JACK]
J27  HDR1X2-2R54-TM-VM  [HDR1X2-2R54-TM-VM]
J29  PH  [PH-1x2-2P0_l]
R215  120R  [R0402]
R216  2.2K  [R0402]
R217  10K  [R0402]
R218  22R  [R0402]
R219  0R  [R0402]
R220  2.2K  [R0402]
R221  0R  [R0402]
R223  0R  [R0402]
R224  0R  [R0402]
Z7  KLXES15AAA1  [ES0402]
Z8  KLXES15AAA1  [ES0402]
Z9  KLXES15AAA1  [ES0402]
Z10  KLXES15AAA1  [ES0402]
Z11  KLXES15AAA1  [ES0402]
Z13  KLXES15AAA1  [ES0402]

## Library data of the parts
C1 C189 C190 = CAP: Voltage: 16V; 规格: 贴片电解电容220uF 20% 16V 尺寸6.3mmX5.8mm 工作寿命：2000H@105℃; 规格编号: VZT221M1CTR-0606ACS; 规格书: 台湾立隆-贴片型铝电解电容.pdf; 价格: 0.566564; 类别: 贴片型铝电解电容; 品牌: 台湾立隆; 生命周期: 量产; 条码: EBF29060148
C2 = CAP_NP: Voltage: 25V; 规格: 贴片电容4.7uF 10% 25V X7R 0603; 规格编号: CL10A475KA8NQNC; 规格书: 三星电容.pdf; 价格: 0.031274; 类别: 贴片电容0603; 品牌: 三星; 生命周期: 量产; 条码: EBF29060162
C3 C4 C6 C7 C9 C11 C14 C17 C19 C23 C26 C28 C30 C33 C36 C58 C60 C61 C63 C65 C67 C68 C70-C72 C74 C150 C152 C153 C155-C157 C162 C164 C165 C167 C168 C172 C175 C179-C182 = CAP_NP: Voltage: 50V; 规格: 贴片电容0.1uF 10% 50V X5R 0402; 规格编号: 0402X104K500NT; 规格书: 风华电容.pdf; 价格: 0.029826; 类别: 贴片电容0402; 品牌: 风华; 生命周期: 量产; 条码: EBF29060118
C5 C10 C151 C154 C163 = CAP_NP: Voltage: 10V; 规格: 贴片电容10uF 20% 10V X5R 0402; 规格编号: CL05A106MP8NUB8; 规格书: 三星电容.pdf; 价格: 0.518415; 类别: 贴片电容0402; 品牌: 三星; 生命周期: 量产; 条码: EBF29060247
C8 C18 C20 C27 C29 C37 C64 C169 C192 = CAP_NP: 规格: 贴片电容NC 预留; 类别: 贴片电容0402; 条码: EBF29060149
C12 C13 C21 C22 C31 C32 C166 C170 C171 C431 = CAP_NP: Voltage: 25V; 规格: 贴片电容10uF 20% 25V X5R 0603; 规格编号: CL10A106MA8NRNC; 规格书: 三星电容.pdf; 价格: 0.109811; 类别: 贴片电容0603; 品牌: 三星; 生命周期: 量产; 条码: EBF29060171
C15 C16 C24 C25 C34 C35 C173 C174 = CAP_NP: Voltage: 10V; 规格: 贴片电容22uF 20% 10V X5R 0603; 规格编号: CL10A226MP8NUNE; 规格书: 三星电容.pdf; 价格: 0.078818; 类别: 贴片电容0603; 品牌: 三星; 生命周期: 量产; 条码: EBF29060163
D1 = DIODE_BI-DIR_TRIG: 规格: TVS二极管 箝位电压21.5V 击穿电压14.4V 反向关断电压13V; 规格书: 伯恩半导体-SMAJ13CA.pdf; 价格: 0.181964; 类别: 贴片TVS; 品牌: 伯恩半导体; 生命周期: 量产; 条码: EBF29140049
D2 = DIODE: 规格: 开关二极管 反向耐压值100V 平均整流电流150mA 正向压降1.25V 150mA 功率500mW; 规格书: 1N4148WT4.pdf; 价格: 0.061637; 类别: 贴片开关二极管; 品牌: 江苏长电; 生命周期: 量产; 丝印: T4; 条码: EBF29140015
F1 = FUSE: 规格: 自恢复保险丝 最大电压46V 最大电流100A 保持电流2A 跳闸电流4A; 规格书: 瑞隆源-自恢复保险丝.pdf; 价格: 0.385618; 类别: 自恢复保险丝; 品牌: 瑞隆源; 生命周期: 量产; 条码: EBF29270006
H1-H4 = SPACER: 规格编号: M3螺丝孔_无铜; 类别: M3螺丝孔; 品牌: 野火科技有限公司; 生命周期: 量产; 条码: EBFCIS220926102704
J1 = DC-044A-20A: 规格: DC-044A-20A DC插座; 规格编号: DC-044A-20A DC; 规格书: DC插座_内径_2MM外径_5.9MM.pdf; 类别: DC电源座; 生命周期: 量产; 条码: EBF29040093
J2 = A1501WV-2P: 规格: ZH1.5直插 镀锡 2P 针座连接器; 规格书: A1501.pdf; 类别: 线对板连接器; 品牌: 长江连接器; 生命周期: 量产; 条码: EBF29040095
L1-L3 L10 = IND: 规格: 贴片电感3.3uH ±20% 3A 直流电阻69mΩ; 规格编号: TMPC0402HP-3R3MG-Z02; 规格书: 台庆-功率电感.pdf; 价格: 1.5992; 类别: 贴片电感0402; 品牌: 台庆; 生命周期: 量产; 条码: EBF29050040
LED4 = LED: 规格: 贴片LED RED 正向电流30mA 反向电压9V 功率消耗350mW 0603; 规格编号: 35B00617LGY-RED; 规格书: LED0603-RED.pdf; 类别: 贴片LED; 品牌: 亿光; 生命周期: 量产; 条码: EBF29140007
Q1 Q12 Q13 = MOSFET_P: 规格: P沟道MOS 导通电阻60mΩ 电流4.1A 3V可驱动; 规格书: 合科泰-AO3407.pdf; 价格: 0.199827; 类别: P-MOS; 品牌: 合科泰; 生命周期: 量产; 丝印: A7; 条码: EBF29280012
Q2 Q3 Q14 = NPN: 规格: 贴片三极管SS8050 集电极电流1.5A 额定功率300mW NPN; 规格书: 江苏长电-SS8050Y1.pdf; 价格: 0.086744; 类别: 贴片三极管SOT-23; 品牌: 江苏长电; 生命周期: 量产; 丝印: Y1; 条码: EBF29090001
R1 R3 R17 R19 R24 R180 R187 R193 R198 R206 = RES: 规格: 贴片电阻1K 1% 1/16W 0402; 规格编号: RI0402L1001FT; 规格书: 合科泰-RI系列电阻.pdf; 类别: 贴片电阻0402; 品牌: 合科泰; 生命周期: 量产; 条码: EBF29070050
R2 = RES: 规格: 贴片电阻3.4K 1% 1/16W 0402; 规格编号: RI0402L3401FT; 规格书: 合科泰-RI系列电阻.pdf; 类别: 贴片电阻0402; 品牌: 合科泰; 生命周期: 量产; 条码: EBF29070186
R4 R203 = RES: 规格: 贴片电阻100K 1% 1/16W 0402; 规格编号: RI0402L1003FT; 规格书: 合科泰-RI系列电阻.pdf; 类别: 贴片电阻0402; 品牌: 合科泰; 生命周期: 量产; 条码: EBF29070054
R5 R182 R188 R195 = RES: 规格: 贴片电阻6.8K 1% 1/16W 0402; 规格编号: RI0402L6801FT; 规格书: 合科泰-RI系列电阻.pdf; 类别: 贴片电阻0402; 品牌: 合科泰; 生命周期: 量产; 条码: EBF29070052
R6 R205 = RES: 规格: 贴片电阻30K 1% 1/16W 0402; 规格编号: RI0402L3002FT; 规格书: 合科泰-RI系列电阻.pdf; 类别: 贴片电阻0402; 品牌: 合科泰; 生命周期: 量产; 条码: EBF29070048
R7 R14 = RES: 规格: 贴片电阻140K 1% 1/16W 0402; 规格编号: RI0402L1403FT; 规格书: 合科泰-RI系列电阻.pdf; 类别: 贴片电阻0402; 品牌: 合科泰; 生命周期: 量产; 条码: EBF29070058
R8 R12 R13 R15 R22 R196 = RES: 规格: 贴片电阻20K 1% 1/16W 0402; 规格编号: 0402WGF2002TCE; 规格书: 厚声-无铅厚膜电阻.pdf; 价格: 0.002473; 类别: 贴片电阻0402; 品牌: 厚声; 生命周期: 量产; 条码: EBF29070223
R9 = RES: 规格: 贴片电阻NC 预留; 类别: 贴片电阻0603; 条码: EBF29070088
R10 R56-R59 R194 = RES: 规格: 贴片电阻0R 1% 1/10W 0603; 规格编号: RI0603L0000FT; 规格书: 合科泰-RI系列电阻.pdf; 类别: 贴片电阻0603; 品牌: 合科泰; 生命周期: 量产; 条码: EBF29070063
R11 R20 = RES: 规格: 贴片电阻115K 1% 1/16W 0402; 规格编号: AC0402FR-07115KL; 规格书: YAGEO国巨厚膜无铅电阻.pdf; 价格: 0.006087; 类别: 贴片电阻0402; 品牌: 国巨; 生命周期: 量产; 条码: EBF29070290
R16 R208 = RES: 规格: 贴片电阻4.7K 1% 1/16W 0402; 规格编号: RI0402L4701FT; 规格书: 合科泰-RI系列电阻.pdf; 类别: 贴片电阻0402; 品牌: 合科泰; 生命周期: 量产; 条码: EBF29070047
R18 R21 R37-R39 R42 R44 R52-R55 R190 R191 R199 R217 R239 = RES: 规格: 贴片电阻10K 1% 1/16W 0402; 规格编号: 0402WGF1002TCE; 规格书: 厚声-无铅厚膜电阻.pdf; 价格: 0.002773; 类别: 贴片电阻0402; 品牌: 厚声; 生命周期: 量产; 条码: EBF29070046
R23 R25 R51 R177 R179 R183 R185 R189 R192 = RES: 规格: 贴片电阻NC 预留; 类别: 贴片电阻0402; 条码: EBF29070087
U1 U2 U33-U35 = MT9700: 规格: 负载开关 工作电压2.4V-5.5V 最大电流2A 过流保护; 规格书: MT9700.pdf; 价格: 0.483492; 类别: 功率开关; 品牌: 西安航天民芯; 生命周期: 量产; 丝印: D00HA-X; 条码: EBF29280004
U3-U5 U36 = TP6327GS6: 规格: DC-DC电源芯片 可输出电流 3A 开关工作频率 600kHz 输出类型 Adjustable 输出电压的路数 1 最小输入电压 3.5V 最大输入电压 18V; 规格书: TP6327GS6.pdf; 价格: 0.962255; 类别: 电源管理-DCDC; 品牌: 台舟; 生命周期: 量产; 条码: EBF29110045
C57 C69 C73 C183 C184 = CAP_NP: Voltage: 10V; 规格: 贴片电容4.7uF 10% 10V X5R 0402; 规格编号: CC0402KRX5R6BB475; 规格书: 国巨-贴片电容.pdf; 价格: 0.059058; 类别: 贴片电容0402; 品牌: 国巨; 生命周期: 量产; 条码: EBF29060248
C59 C62 C186 C191 = CAP_NP: voltage: 50V; 规格: 贴片电容0.1uF 10% 50V X5R 0402; 规格编号: 0402X104K500NT; 规格书: 风华电容.pdf; 价格: 0.029826; 类别: 贴片电容0402; 品牌: 风华; 生命周期: 量产; 条码: EBF29060118
C66 C185 C187 = CAP_NP: Voltage: 10V; 规格: 贴片电容1uF 10% 10V X5R 0402; 规格编号: 0402X105K100NT; 规格书: 风华电容.pdf; 价格: 0.01191; 类别: 贴片电容0402; 品牌: 风华; 生命周期: 量产; 条码: EBF29060121
J5 J27 = 1X2PIN: 规格: 蓝色直插单排排针 总PIN数2 间距2.54mm; 规格编号: HDR1X2-2R54-TM-VM-BLUE; 规格书: 州日_单排针_直插_2P54.pdf; 价格: 0.02; 类别: 直插单排排针; 品牌: 州日; 生命周期: 量产; 条码: EBF29020019
J6 = CON4: 规格: 直针XH2.54-4P 间距2.54MM 拔插式 接插件 直插; 规格书: 博穆精密-XH2.54.pdf; 价格: 0.041116; 可替代料: EBF29040012; 类别: XH连接器; 品牌: 博穆精密; 生命周期: 量产; 条码: EBF29040012
LED1-LED3 = LED: 规格: 贴片LED BLUE 正向电流30mA 反向电压9V 功率消耗350mW 0603; 规格编号: 35B00617LGY-BLUE; 规格书: LED0603-BLUE.pdf; 类别: 贴片LED; 品牌: 亿光; 生命周期: 量产; 条码: EBF29140008
R40 R41 = RES: 规格: 贴片电阻560R 1% 1/16W 0402; 规格编号: 0402WGF5600TCE; 规格书: 厚声-无铅厚膜电阻.pdf; 价格: 0.002258; 类别: 贴片电阻0402; 品牌: 厚声; 生命周期: 量产; 条码: EBF29070272
R43 R211 R212 R232 = RES: 规格: 贴片电阻100R 1% 1/16W 0402; 规格编号: RI0402L1000FT; 规格书: 合科泰-RI系列电阻.pdf; 类别: 贴片电阻0402; 品牌: 合科泰; 生命周期: 量产; 条码: EBF29070053
R45 R48 R49 = RES: 规格: 贴片电阻470R 1% 1/16W 0402; 规格编号: 0402WGF4700TCE; 规格书: 厚声-无铅厚膜电阻.pdf; 价格: 0.002728; 类别: 贴片电阻0402; 品牌: 厚声; 生命周期: 量产; 条码: EBF29070284
R46 R47 R60-R65 R209 R210 R218 = RES: 规格: 贴片电阻22R 1% 1/16W 0402; 规格编号: RI0402L22R0FT; 规格书: 合科泰-RI系列电阻.pdf; 类别: 贴片电阻0402; 品牌: 合科泰; 生命周期: 量产; 条码: EBF29070181
SW1-SW4 = SW_PB_ESW: 备注: 修正封装; 规格: 3×4×2.5 160gf 轻触开关 白色; 规格编号: TS-1089S-AR02516; 规格书: 讯普3×4×2.5160GF轻触开.pdf; 价格: 0.168282; 类别: 贴片轻触开关; 品牌: 讯普; 生命周期: 量产; 条码: EBF29310006
U8 = W25QXX_8P: 规格: nor Flash 大小32Mb (4M x 8) 接口SPI-4I/O 工作电压1.7V~1.95V; 规格编号: W25Q32JWSSIQ; 规格书: 华邦W25Q32JWSSIQ.pdf; 价格: 2.95; 类别: 存储器-Flash; 品牌: 华邦; 生命周期: 量产; 条码: EBF2950030
U9 U10 = 74LVC1G125: 规格: 时钟缓冲器 驱动器 具有三态输出 允许工作电压为3.3V 5.5V 典型工作电流100mA; 规格书: 74LVC1G125GW.pdf; 价格: 0.182409; 类别: 隔离器件; 品牌: 安世; 生命周期: 量产; 丝印: VM; 条码: EBF29170001
U11 = IRM-V838M3-C_TR1: 规格: 侧贴红外遥控接收头 工作电压2.7V~5.5V 兼容TTL与CMOS; 规格书: IRM-V838M3-C_TR1.pdf; 类别: 红外接收头; 品牌: 亿光; 生命周期: 量产; 条码: EBF29230005
D7 D12-D18 D35 D36 D47-D54 Z1-Z5 Z7-Z11 Z13 Z23 = DIODE_BI-DIR_TRIG: 规格: 用于 USB3.0、HDMI 0.5pF、5V、±15kV ESD 保护二极管; 规格书: KLXES15AAA1.pdf; 价格: 0.09719; 类别: 贴片ESD; 品牌: 永裕泰; 生命周期: 量产; 条码: EBF29140063
D6 = BAT54C: 规格: 肖特基二极管 直流反向耐压30V 平均整流电流200mA 正向压降1V@100mA SOT-23; 规格书: BAT54C.pdf; 价格: 0.068489; 类别: 贴片肖特基二极管; 品牌: 萨科微; 生命周期: 量产; 丝印: KL3; 条码: EBF29140014
D8-D11 = DIODE_BI-DIR_TRIG: 规格: TVS二极管 箝位电压24.4V 击穿电压16.7V 反向关断电压15V; 规格书: 君耀电子-SMBJ15CA.pdf; 价格: 0.197164; 类别: 贴片TVS; 品牌: 君耀电子; 生命周期: 量产; 条码: EBF29140024
J7 = 1.25T-2A: 规格: GH1.25直插 2P针座连接器; 规格书: 1.25T-2A.pdf; 类别: 线对板连接器; 品牌: 创都; 生命周期: 量产; 条码: EBF29040105
J8 = CON6: 规格: 绿色插拔式接线端子 间距3.81mm 90度弯针 6PIN; 规格编号: WJ15EDGRC-3.81-6P; 规格书: 康奈克斯电气-绿色端子弯针插座.pdf; 价格: 0.301748; 类别: 绿色插拔式接线端子; 品牌: 康奈克斯电气; 生命周期: 量产; 条码: EBF29040013
J9 = TF_Card: 规格: MICRO SD 卡座 TF T-Flash 外焊 双压片 自弹贴片; 规格编号: TF-015; 规格书: 硕方-TF-015.pdf; 价格: 0.48; 可替代料: EBF29040003; 类别: SD卡连接器; 品牌: 硕方; 生命周期: 量产; 条码: EBF29040003
R50 R66 R178 R181 R184 R186 R201 R202 R204 R219 R221 R223 R224 = RES: 规格: 贴片电阻0R 1% 1/16W 0402; 规格编号: RI0402L000FT; 规格书: 合科泰-RI系列电阻.pdf; 类别: 贴片电阻0402; 品牌: 合科泰; 生命周期: 量产; 条码: EBF29070049
U12 = RX8010SJ: 规格: 工作电压1.6V~5.5V 日期格式YY-MM-DD 时间格式HH:MM:SS 接口类型I2C 电流消耗350nA~@5V; 规格书: 爱普生RX8010SJ.pdf; 价格: 34.17; 类别: 实时时钟芯片; 品牌: 爱普生; 生命周期: 量产; 条码: EBF29180003
U13 = MAX3232CSE: 规格: RS232芯片 收发器 驱动器/接收器数：2/2 协议类别RS232 电源电压3V~5.5V 数据速率235kbps; 规格编号: MAX3232CSE+T; 规格书: MAX3232CSE.pdf; 价格: 7.73; 类别: RS232芯片; 品牌: 美信; 生命周期: 量产; 丝印: MAX3232; 条码: EBF29150006
J32 J34-J36 = 1X4PIN: 规格: 直针PH2.0-4P 间距2.0MM 拔插式 接插件; 规格书: 博穆精密-PH2.0.pdf; 价格: 0.017; 可替代料: EBF29020025; 类别: PH连接器; 品牌: 博穆精密; 生命周期: 量产; 条码: EBF29020025
R222 R225 R233-R238 = RES: 规格: 贴片电阻510R 1% 1/16W 0402; 规格编号: 0402WGF5100TCE; 规格书: 厚声-无铅厚膜电阻.pdf; 价格: 0.003791; 类别: 贴片电阻0402; 品牌: 厚声; 生命周期: 量产; 条码: EBF29070293
J20 J21 = FPC-24P: 规格: FPC连接器 针脚数24 间距0.5mmm 下接 卧贴 翻盖式; 规格编号: AFC01-S24FCA-00; 规格书: 钜硕电子-FPC间距0.5mm.pdf; 价格: 0.368739; 可替代料: EBF29040059; 类别: FPC连接器; 品牌: 钜硕电子; 生命周期: 量产; 条码: EBF29040059
J22 = FPC-30P: 规格: FPC连接器 针脚数30 间距0.5mm 高度2.0mm 下接 卧贴 翻盖式; 规格编号: FPC-05F-30PH20; 规格书: FPC-05F-NPH20.pdf; 类别: FPC连接器; 品牌: 讯普; 生命周期: 量产; 条码: EBF29040079
J23 = 1X6PIN: 规格: 直针PH2.0-6P 间距2.0MM 拔插式 接插件; 规格书: 博穆精密_PH2.0-A.pdf; 价格: 0.0228; 可替代料: EBF29020026; 类别: PH连接器; 品牌: 博穆精密; 生命周期: 量产; 条码: EBF29020026
C176-C178 = CAP_NP: Voltage: 50V; 规格: 贴片电容33pF 5% 50V 0402; 规格编号: 0402CG330J500NT; 规格书: 风华电容.pdf; 类别: 贴片电容0402; 品牌: 风华; 生命周期: 量产; 条码: EBF29060298
J24 = MINI-PCIE: 规格: MINI PCIE插座 引脚数：52P; 规格编号: PCIE-52P56H; 规格书: XUNPU(讯普)_52PMINIPCIE插座.pdf; 价格: 1.935; 可替代料: EBF29040055; 类别: 金手指连接器; 品牌: 讯普; 生命周期: 量产; 条码: EBF29040055
R200 = RES: 规格: 贴片电阻15K 1% 1/16W 0402; 规格编号: RI0402L1502FT; 规格书: 合科泰-RI系列电阻.pdf; 类别: 贴片电阻0402; 品牌: 合科泰; 生命周期: 量产; 条码: EBF29070222
R213 R214 = RES: 规格: 贴片电阻2.2R 1% 1/16W 0402; 规格编号: 0402WGF220KTCE; 规格书: 厚声-无铅厚膜电阻.pdf; 价格: 0.003072; 类别: 贴片电阻0402; 品牌: 厚声; 生命周期: 量产; 条码: EBF29070280
SS1 SS2 = SPACER: 规格: SMT贴片螺母M2 高度3MM 台阶外径：4.5MM 整体高度：4.5MM 焊接孔外径：3MM; 规格编号: ZIY01-001; 规格书: 雄和远景_SMTWE2040CTJ.pdf; 类别: 贴片螺母; 品牌: 雄和远景; 生命周期: 量产; 条码: EBF500026
U37 = SIM-7-1: 规格: nano sim卡座; 规格编号: HYC63-SIM07-137; 规格书: 华宇创_NANOSIMPUSH1.37H带CDPIN带柱.pdf; 价格: 1.48; 可替代料: EBF29040054; 类别: SIM卡座连接器; 品牌: 华宇创; 生命周期: 量产; 条码: EBF29040054
U38 = NUP5120-D: 规格: 防静电保护ESD二极管 击穿电压6.2V 反向关断电压5V 封装SOT-523; 规格书: 安森美_NUP5120X6T1G.pdf; 价格: 0.39; 类别: 贴片ESD; 品牌: 安森美; 生命周期: 量产; 条码: EBF29140034
C188 = CAP_NP: Voltage: 50V; 规格: 贴片电容100pF 5% 50V C0G 0603; 规格编号: 0603CG101J500NT; 规格书: 风华电容.pdf; 价格: 0.014181; 类别: 贴片电容0603; 品牌: 风华; 生命周期: 量产; 条码: EBF29060132
J25 = MIC_JACK: 规格: 音频插座 耳机插座 双声道 3.5mm耳机座 5脚 绿; 规格书: 星坤-音频连接器.pdf; 价格: 0.24; 可替代料: EBF29020024; 类别: 耳机座; 品牌: 中国星坤; 生命周期: 量产; 条码: EBF29020024
J26 = MIC_JACK: 规格: 音频插座 耳机插座 双声道 3.5mm耳机座 5脚 粉; 规格书: 星坤-音频连接器.pdf; 价格: 0.24; 可替代料: EBF29020023; 类别: 耳机座; 品牌: 中国星坤; 生命周期: 量产; 条码: EBF29020023
J29 = 1X2PIN: 规格: 直针PH2.0-2P 间距2.0MM 拔插式 接插件; 规格编号: PH-2A; 规格书: 博穆精密_PH2.0-A.pdf; 价格: 0.019031; 可替代料: EBF29040005; 类别: PH连接器; 品牌: 博穆精密; 生命周期: 量产; 条码: EBF29040005
R215 = RES: 规格: 贴片电阻120R 1% 1/16W 0402; 规格编号: 0402WGF1200TCE; 规格书: 厚声-无铅厚膜电阻.pdf; 价格: 0.002198; 类别: 贴片电阻0402; 品牌: 厚声; 生命周期: 量产; 条码: EBF29070275
R216 R220 = RES: 规格: 贴片电阻2.2K 1% 1/16W 0402; 规格编号: RI0402L2201FT; 规格书: 合科泰-RI系列电阻.pdf; 类别: 贴片电阻0402; 品牌: 合科泰; 生命周期: 量产; 条码: EBF29070051

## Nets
3V3_EDP: C163.1 C164.1 J22.12 J22.13 J23.1 R189.1 R190.1 R191.1 U35.1(OUT)
5V0_CAM_1: C151.1 C152.1 J20.1 J20.2 J20.3 U33.1(OUT)
5V0_CAM_2: C154.1 C155.1 J21.1 J21.2 J21.3 U34.1(OUT)
12V_EDP: C166.1 C167.1 J22.26 J22.27 J22.28 J22.29 Q13.3(DRAIN)
GND: C1.2 C2.2 C3.2 C4.2 C5.2 C6.2 C9.2 C10.2 C11.2 C12.2 C13.2 C14.2 C15.2 C16.2 C17.2 C18.1 C21.2 C22.2 C23.2 C24.2 C25.2 C26.2 C27.1 C30.2 C31.2 C32.2 C33.2 C34.2 C35.2 C36.2 C37.1 C57.2 C58.2 C59.2 C60.2 C61.2 C62.2 C63.2 C64.2 C65.2 C66.2 C67.2 C68.2 C69.2 C70.2 C73.2 C74.2 C150.2 C151.2 C152.2 C153.2 C154.2 C155.2 C162.2 C163.2 C164.2 C166.2 C167.2 C170.2 C171.2 C172.2 C173.2 C174.2 C175.2 C176.2 C177.2 C178.2 C181.2 C182.2 C183.2 C184.2 C185.2 C186.2 C187.2 C191.2 C192.2 C431.2 D1.1 D2.2(A) D7.1 D8.1 D9.1 D10.1 D11.1 D12.1 D13.1 D14.1 D15.1 D16.1 D17.1 D18.1 D35.1 D36.1 D47.1 D48.1 D49.1 D50.1 D51.1 D52.1 D53.1 D54.1 J1.1 J1.2 J1.3 J1.5 J2.2 J5.1 J6.4 J7.2 J8.2 J8.5 J9.6(VSS) J9.10(GND10) J9.11(GND11) J9.12(GND12) J9.13(GND13) J20.4 J20.18 J20.21 J20.23 J20.24 J20.25(SH1) J20.26(SH2) J21.4 J21.23 J21.24 J21.25(SH1) J21.26(SH2) J22.2 J22.5 J22.8 J22.11 J22.15 J22.16 J22.18 J22.19 J22.20 J22.21 J22.31(SH1) J22.32(SH2) J23.6 J24.4(GND9) J24.9(GND1) J24.15(GND2) J24.18(GND10) J24.21(GND3) J24.26(GND11) J24.27(GND4) J24.29(GND5) J24.34(GND12) J24.35(GND6) J24.37(GND7) J24.40(GND13) J24.43(GND8) J24.50(GND14) J24.53 J24.54 J32.4 J34.4 J35.4 J36.4 Q2.2(EMITTER) Q3.2(EMITTER) Q14.2(EMITTER) R2.2 R5.2 R6.2 R8.2 R13.2 R15.2 R18.2 R21.2 R22.2 R25.2 R182.2 R188.2 R192.1 R195.2 R199.2 R205.2 R219.2 R220.2 R221.2 SS1.1(NC) SS2.1(NC) SW1.1(A1) SW1.2(A2) SW2.1(A1) SW2.2(A2) SW3.1(A1) SW3.2(A2) SW4.1(A1) SW4.2(A2) U1.2(GND) U2.2(GND) U3.1(GND) U4.1(GND) U5.1(GND) U8.4(GND) U9.1(\\~{O}E) U9.3(GND) U10.1(\\~{O}E) U10.3(GND) U11.1(GND1) U11.4(GND2) U12.4(GND) U13.15(GND) U33.2(GND) U34.2(GND) U35.2(GND) U36.1(GND) U37.5(GND) U37.8(SH1) U37.9(SH2) U37.10(SH3) U37.11(SH4) U38.2 Z1.1 Z2.2 Z3.2 Z4.1 Z5.1 Z7.1 Z8.1 Z9.1 Z10.1 Z11.1 Z13.1 Z23.1 ; also on sheet 1 5 6 7 8 9 10 11
VCC3V3_SD: C73.1 C74.1 J9.4(VDD) ; also on sheet 6
VCC3V3_SYS: C8.1 C15.1 C16.1 C17.1 L1.2 R4.1 U1.5(IN) U35.5(IN) ; also on sheet 5 11
VCC5V0_SYS: C20.1 C24.1 C25.1 C26.1 L2.2 R11.1 R16.1 U2.5(IN) U33.5(IN) U34.5(IN) ; also on sheet 6 11
VCC5V0_SYS_2: C29.1 C34.1 C35.1 C36.1 L3.2 R10.1 R20.1 ; also on sheet 5 9
VCC_1V8: C57.1 C58.1 R37.1 R38.1 U8.8(VCC) ; also on sheet 6 8
VCC_12V: C1.1 C2.1 C3.1 C12.1 C13.1 C14.1 C21.1 C22.1 C23.1 C31.1 C32.1 C33.1 C165.1 C170.1 C171.1 C172.1 D1.2 F1.2 Q12.3(DRAIN) R7.1 R9.1 R14.1 R23.1 R196.1 U3.3(VIN) U4.3(VIN) U5.3(VIN) U36.3(VIN) ; also on sheet 5
VCC_RTC: R51.2 ; also on sheet 6
VCCA_1V8: R239.2 ; also on sheet 6
VCCIO_ACODEC: C186.1 C191.1 R215.1 R217.1 ; also on sheet 6
VDD_3V3: C5.1 C6.1 C59.1 C62.1 C69.1 C431.1 D6.2 J32.1 J34.1 J35.1 J36.1 LED1.2(ANODE) LED2.2(ANODE) LED3.2(ANODE) R39.1 R42.1 R44.1 R47.2 R52.1 R53.1 R54.1 R55.1 U1.1(OUT) U9.5(VCC) U10.5(VCC) U13.16(VCC) ; also on sheet 1 7 8 9 10 11
VDD_5V: C10.1 C11.1 U2.1(OUT) ; also on sheet 10
CAM0_nRST: J20.22 ; also on sheet 6
CAM0_PWDN: J20.15 ; also on sheet 6
CAM0_PWR_EN: R180.1 ; also on sheet 6
CAM1_nRST: J21.22 ; also on sheet 6
CAM1_PWDN: J21.15 ; also on sheet 6
CAM1_PWR_EN: R187.1 ; also on sheet 6
CSI_RX_D2N_S0: J20.17 R179.2
CSI_RX_D2N_S1: J21.12 R181.2
CSI_RX_D2P_S0: J20.16 R177.2
CSI_RX_D2P_S1: J21.11 R178.2
CSI_RX_D3N_S0: J20.20 R185.2
CSI_RX_D3N_S1: J21.8 R186.2
CSI_RX_D3P_S0: J20.19 R183.2
CSI_RX_D3P_S1: J21.7 R184.2
DBG_RX: R41.2 U10.2(A)
DBG_RXD: J6.3 R41.1 Z3.1
DBG_TX: R40.2 U9.4(Y)
DBG_TXD: J6.2 R40.1 Z2.1
DM4: D35.2 J24.36(USB-D-) R213.1
DP4: D36.2 J24.38(USB-D+) R214.1
EDP_AUXN: C157.2 J22.10 R192.2
EDP_AUXP: C156.2 J22.9 R189.2
EDP_BL_EN: J22.22 ; also on sheet 6
EDP_BL_PWM: J22.23 ; also on sheet 6
EDP_HPDIN_M0: J22.17 ; also on sheet 6
EDP_PWR_EN: R193.1 R198.1 ; also on sheet 6
EDP_TP_INT: J23.2 R190.2 ; also on sheet 6
EDP_TP_RESET: J23.3 R191.2 ; also on sheet 6
EDP_TX_AUXN: C157.1 ; also on sheet 6
EDP_TX_AUXP: C156.1 ; also on sheet 6
EDP_TX_D0N: J22.6 ; also on sheet 6
EDP_TX_D0P: J22.7 ; also on sheet 6
EDP_TX_D1N: J22.3 ; also on sheet 6
EDP_TX_D1P: J22.4 ; also on sheet 6
EXT_PWR_EN: R1.1 R3.1 R19.1 R24.1 ; also on sheet 6
FAN: C30.1 Q1.2(SOURCE) R9.2 R10.2 R12.1
FSPI_CLK: U8.6(CLK) ; also on sheet 6
FSPI_CS0n: U8.1(~{CS}) ; also on sheet 6
FSPI_D0: J5.2 U8.5(DI/IO0) ; also on sheet 6
FSPI_D1: U8.2(DO/IO1) ; also on sheet 6
FSPI_D2: R37.2 U8.3(~{WP}/IO2) ; also on sheet 6
FSPI_D3: R38.2 U8.7(HOLD/IO3) ; also on sheet 6
GPIO2_B7: R48.2 ; also on sheet 6
GPIO2_C0: R49.2 ; also on sheet 6
HP_DET_L: C187.1 R218.1 ; also on sheet 6
HP_SNS: J25.1 J26.1 R219.1 R221.1 ; also on sheet 6
HPL_OUT: C189.1 ; also on sheet 6
HPR_OUT: C190.1 ; also on sheet 6
HUB_DM4: R213.2 ; also on sheet 9
HUB_DP4: R214.2 ; also on sheet 9
I2C0_SCL_PMIC: U12.6(SCL) ; also on sheet 6
I2C0_SDA_PMIC: U12.5(SDA) ; also on sheet 6
I2C1_SCL: J20.6 ; also on sheet 6 11
I2C1_SDA: J20.5 ; also on sheet 6 11
I2C2_SCL_M1: R222.2 ; also on sheet 6
I2C2_SDA_M1: R233.2 ; also on sheet 6
I2C3_SCL_M0: R237.2 ; also on sheet 6
I2C3_SDA_M0: R238.2 ; also on sheet 6
I2C4_SCL_M0: J23.4 ; also on sheet 6
I2C4_SDA_M0: J23.5 ; also on sheet 6
I2C5_SCL_M0: J21.6 ; also on sheet 6 11
I2C5_SDA_M0: J21.5 ; also on sheet 6 11
MIC_INN: C188.2 J27.1 R220.1 Z10.2 ; also on sheet 6
MIC_INP: C188.1 J26.2 J26.3 J26.4 J26.5 J27.2 R216.2 Z7.2 ; also on sheet 6
MINIPCIE_3V3: C169.1 C173.1 C174.1 C175.1 C181.1 C182.1 C183.1 C184.1 J24.2(VBAT1) J24.24(VBAT5) J24.39(VBAT2) J24.41(VBAT3) J24.52(VBAT4) L10.2 R203.1 R208.1
MINIPCIE_nWDISABLE: R211.2 ; also on sheet 6
MIPI_CSI_RX_CLK0N: J20.10 ; also on sheet 6
MIPI_CSI_RX_CLK0P: J20.9 ; also on sheet 6
MIPI_CSI_RX_CLK1N: J21.10 ; also on sheet 6
MIPI_CSI_RX_CLK1P: J21.9 ; also on sheet 6
MIPI_CSI_RX_D0N: J20.12 ; also on sheet 6
MIPI_CSI_RX_D0P: J20.11 ; also on sheet 6
MIPI_CSI_RX_D1N: J20.8 ; also on sheet 6
MIPI_CSI_RX_D1P: J20.7 ; also on sheet 6
MIPI_CSI_RX_D2N: R179.1 R181.1 ; also on sheet 6
MIPI_CSI_RX_D2P: R177.1 R178.1 ; also on sheet 6
MIPI_CSI_RX_D3N: R185.1 R186.1 ; also on sheet 6
MIPI_CSI_RX_D3P: R183.1 R184.1 ; also on sheet 6
PCIE20_CLKREQn_M0: R210.1 ; also on sheet 6
PCIE20_PERSTn_M0: R212.2 ; also on sheet 6
PCIE20_REFCLKN: J24.11(VDD-EXT) ; also on sheet 6
PCIE20_REFCLKP: J24.13(RESERVED) ; also on sheet 6
PCIE20_RXN: J24.23(UART-RXD) ; also on sheet 6
PCIE20_RXP: J24.25(UART-RTS) ; also on sheet 6
PCIE20_TXN: C179.1 ; also on sheet 6
PCIE20_TXP: C180.1 ; also on sheet 6
PCIE20_WAKEn_M0: R209.1 ; also on sheet 6
PCIE_PWREN_EN: R206.1 ; also on sheet 6
PE_TXN: C179.2 J24.31(UART-TXD)
PE_TXP: C180.2 J24.33(PERST2)
PWM2_M0: R17.1 ; also on sheet 6
PWM3_IR: C64.1 R46.1 ; also on sheet 6
PWRON_KEY: C60.1 SW1.3(B1) SW1.4(B2) Z1.2 ; also on sheet 6
RECOVERY: R43.2 ; also on sheet 6
RESET_KEY: C61.1 SW2.3(B1) SW2.4(B2) Z4.2 ; also on sheet 6
RX8010_nIRQ1: U12.7(/IRQ1) ; also on sheet 6
RX8010_nIRQ2: U12.3(/IRQ2) ; also on sheet 6
RXD1_232: D9.2 R58.1 U13.13(R1IN)
RXD2_232: D8.2 R56.1 U13.8(R2IN)
SARADC_VIN1: R232.2 ; also on sheet 6
SDMMC0_CLK: R63.1 ; also on sheet 6
SDMMC0_CMD: R62.1 ; also on sheet 6
SDMMC0_D0: R64.1 ; also on sheet 6
SDMMC0_D1: R65.1 ; also on sheet 6
SDMMC0_D2: R60.1 ; also on sheet 6
SDMMC0_D3: R61.1 ; also on sheet 6
SDMMC0_DET_L: R66.1 ; also on sheet 6
SIM_CLK0: J24.12(USIM-CLK) R202.1
SIM_DATA0: J24.10(USIM-DATA) R204.1
SIM_RST0: J24.14(USIM-RST) R201.1
SIM_VDD: J24.8(USIM-VDD) R200.1 U37.1(VCC) U38.1
SPKN_OUT: R224.1 Z13.2 ; also on sheet 6
SPKP_OUT: R223.1 Z11.2 ; also on sheet 6
TXD1_232: D11.2 R59.1 U13.14(T1OUT)
TXD2_232: D10.2 R57.1 U13.7(T2OUT)
UART2_RX_M0_DEBUG: R42.2 U10.4(Y) ; also on sheet 6
UART2_TX_M0_DEBUG: R39.2 U9.2(A) ; also on sheet 6
UART3_RX_M1: R52.2 U13.9(R2OUT) ; also on sheet 6
UART3_TX_M1: R53.2 U13.10(T2IN) ; also on sheet 6
UART4_RX_M1: R54.2 U13.12(R1OUT) ; also on sheet 6
UART4_TX_M1: R55.2 U13.11(T1IN) ; also on sheet 6
UART7_RX_M0: R225.2 ; also on sheet 6
UART7_TX_M0: R234.2 ; also on sheet 6
UART9_RX_M1: R235.2 ; also on sheet 6
UART9_TX_M1: R236.2 ; also on sheet 6
USER_LED: R45.2 ; also on sheet 6
N02088: F1.1 J1.4
N03633: C7.1 U3.6(BOOT)
N03641: C7.2 L1.1 U3.2(SW)
N03801: C8.2 R4.2 R6.1 U3.4(FB)
N28501: C28.1 U5.6(BOOT)
N28533: C28.2 L3.1 U5.2(SW)
N15118698: C4.1 R1.2 U1.4(EN)
N15119063: R2.1 U1.3(ISET)
N15122947: C9.1 R3.2 U2.4(EN)
N15123057: R5.1 U2.3(ISET)
N15659726: C18.2 R7.2 R8.1 U3.5(EN)
N15830872: C190.2 J25.3 J25.5 Z9.2
N15830941: C189.2 J25.2 R218.2 Z8.2
N15838979: J25.4 R217.2
N15851038: C185.1 R215.2 R216.1
N15852295: J29.1 R223.2
N15852481: J29.2 R224.2
N16735828: LED1.1(CATHODE) R45.1
N16735933: LED2.1(CATHODE) R48.1
N16793147: D12.2 J9.1(DAT2) R60.2
N16793149: D16.2 J9.7(DAT0) R64.2
N16793151: D15.2 J9.5(CLK) R63.2
N16793153: D14.2 J9.3(CMD) R62.2
N16793155: D13.2 J9.2(CD/DAT3) R61.2
N16793157: D17.2 J9.8(DAT1) R65.2
N16793300: D18.2 J9.9(CD) R66.2
N16795570: LED3.1(CATHODE) R49.1
N16795883: C37.2 R23.2 R24.2 R25.1 U5.5(EN)
N16811933: J24.1(MIC-P) R208.2 R209.2
N16823854: J24.7(SPK-N) R210.2
N16928945: J24.20(W-DISABLE) R211.1
N16929135: J24.22(PERST1) R212.1
N16980859: C178.1 R201.2 U37.2(RST) U38.6
N16980861: C177.1 R202.2 U37.3(CLK) U38.4
N16980863: C176.1 R200.2 R204.2 U37.7(I/O) U38.5
N17405290: C29.2 R20.2 R22.1 U5.4(FB)
N17423559: C19.1 U4.6(BOOT)
N17423580: C19.2 L2.1 U4.2(SW)
N17423608: C27.2 R14.2 R15.1 U4.5(EN)
N17423737: C20.2 R11.2 R13.1 U4.4(FB)
N17454508: C71.2 U13.1(C1+)
N17454513: C71.1 U13.3(C1-)
N17455367: C72.2 U13.4(C2+)
N17455372: C72.1 U13.5(C2-)
N17455499: C70.1 U13.6(V-)
N17455508: C68.1 U13.2(V+)
N17592125: C168.1 U36.6(BOOT)
N17592129: C168.2 L10.1 U36.2(SW)
N17592172: C169.2 R203.2 R205.1 U36.4(FB)
N17592286: R206.2 U36.5(EN)
N17685591: C165.2 Q12.1(GATE) Q13.1(GATE) Q14.3(COLLECTOR) R196.2
N17685601: Q14.1(BASE) R198.2 R199.1
N17685851: Q13.2(SOURCE) R194.2
N17690217: R195.1 U35.3(ISET)
N17690290: C162.1 R193.2 U35.4(EN)
N17697880: R182.1 U33.3(ISET)
N17697953: C150.1 R180.2 U33.4(EN)
N17731599: J8.6 R59.2
N17731608: J8.4 R58.2
N17731627: J8.1 R56.2
N17750545: Q1.1(GATE) Q2.3(COLLECTOR) R12.2
N17750554: D2.1(K) J2.1 Q1.3(DRAIN)
N17750632: Q2.1(BASE) R17.2 R18.1
N17759502: C67.1 D6.3 U12.8(VDD)
N17861933: C65.1 C66.1 R47.1 U11.2(VCC)
N17863087: R44.2 R46.2 U11.3(OUT)
N17946485: C63.1 R43.1 SW3.3(B1) SW3.4(B2) Z5.2
N17975561: D7.2 J7.1 R50.2 R51.1
N18091011: D6.1 R50.1
N18115454: R188.1 U34.3(ISET)
N18115527: C153.1 R187.2 U34.4(EN)
N18245213: LED4.1(CATHODE) Q3.3(COLLECTOR)
N18245628: LED4.2(ANODE) R16.2
N18246356: Q3.1(BASE) R19.2 R21.1
N18288623: C192.1 R232.1 R239.1 SW4.3(B1) SW4.4(B2) Z23.2
N18348384: J8.3 R57.2
N18386455: Q12.2(SOURCE) R194.1
N18494968: D48.2 J34.2 R237.1
N18494970: D47.2 J34.3 R238.1
N18495009: D50.2 J32.2 R222.1
N18495011: D49.2 J32.3 R233.1
N18495097: D52.2 J35.2 R234.1
N18495099: D51.2 J35.3 R225.1
N18495175: D54.2 J36.2 R236.1
N18495177: D53.2 J36.3 R235.1

Not connected (* = marked no-connect by the designer): H1 1(NC)*; H2 1(NC)*; H3 1(NC)*; H4 1(NC)*; J6 1*; J20 13* 14*; J21 13* 14* 16* 17* 18* 19* 20* 21*; J22 1* 14* 24* 25* 30*; J24 3(MIC-N)* 5(SPK-P)* 6(NC1)* 16(RESERVED6)* 17(RESERVED5)* 19(WAKEUP-IN)* 28(UART-CTS)* 30(UART-DCD)* 32(WAKEUP-OUT)* 42(LED-WWAN)* 44(USIM-PRESENCE)* 45(RESERVED1)* 46(UART-DTR)* 47(RESERVED2)* 48(NC2)* 49(RESERVED3)* 51(RESERVED4)*; U12 1(NC1)* 2(NC2)*; U37 4(CD)* 6(VPP)*; U38 3*

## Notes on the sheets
sheet 12
- MIPI CSI 0 PORT
- MIPI CSI 1 PORT
- GPIO3_A2
- GPIO3_A7
- GPIO2_B0
- GPIO2_A7
- Channel Gating
- MIPI CSI Power
- Default:2Lane
- GPIO1_B1
- 1A限流
- GPIO3_D4
- 1A限流
sheet 13
- MINI PCIE POWER
- SIM CARD
- 3.3v 3A
- FB 0.765V
- GPIO0_D4
- MINI PCIE
- GPIO3_B5
sheet 14
- EarPhone PORT
- MIC PORT
- 耳机插入时HP_DET口为低电平
  耳机未插入时HP_DET口为高电平
- GPIO1_B2
- KLXES15AAA1 *2
- SPK PORT
sheet 15
- RTC
- GPIO3_A5
- GPIO3_A6
- RS232 PORT
- Bidirectional Device
- Bidirectional Device
- SD Card
- KLXES15AAA1 *8
sheet 16
- I2C PORT 0
- UART PORT 0
- KLXES15AAA1*2
- KLXES15AAA1*2
- I2C PORT 1
- UART PORT 1
- KLXES15AAA1*2
- KLXES15AAA1*2
sheet 17
- DC IN : 12V
- SYSTEM Power SW And OCP
- 2A限流
- VCC3VS_SYS
- 3.3v 3A
- 1A限流
- FB 0.765V
- EN:1.3V(TYP)
- UVLO:10.5V
- SYS Power LED
- CPU FAN
- VCC5V0_SYS
- 贴片功率电感
- 5.2V 3A
- FB 0.765V
- EN:1.3V(TYP)
- UVLO:10.5V
- VCC5V0_SYS_2
- 贴片功率电感
- 5.2V 3A
- FB 0.765V
- Fix Hole
sheet 18
- eDP1.3 PORT
- EDP TOUCH
- GPIO3_B0
- GPIO3_B6
- GPIO0_C7
- PWM0_M0
- EDP Power
- GPIO1_B0
- 1A限流
- 1.5A熔断
sheet 19
- NOR SPI FLASH
- 上电或复位后，短接过孔
  进入MaskRom模式
- Button
- DEBUG
- 短按开机   长按关机
- IR Receiver
- LED
- 用户LED
- GPIO0_C0
